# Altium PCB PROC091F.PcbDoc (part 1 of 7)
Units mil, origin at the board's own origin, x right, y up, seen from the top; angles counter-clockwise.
Board outline 3590.95 x 906.17 mil, 8 copper layers (Top Layer, GND1, Sig1, PWR1, PWR2, Sig2, GND2, Bottom Layer), stack 63.146 mil thick; 420 components, 316 nets, 1432 pads, 774 vias.
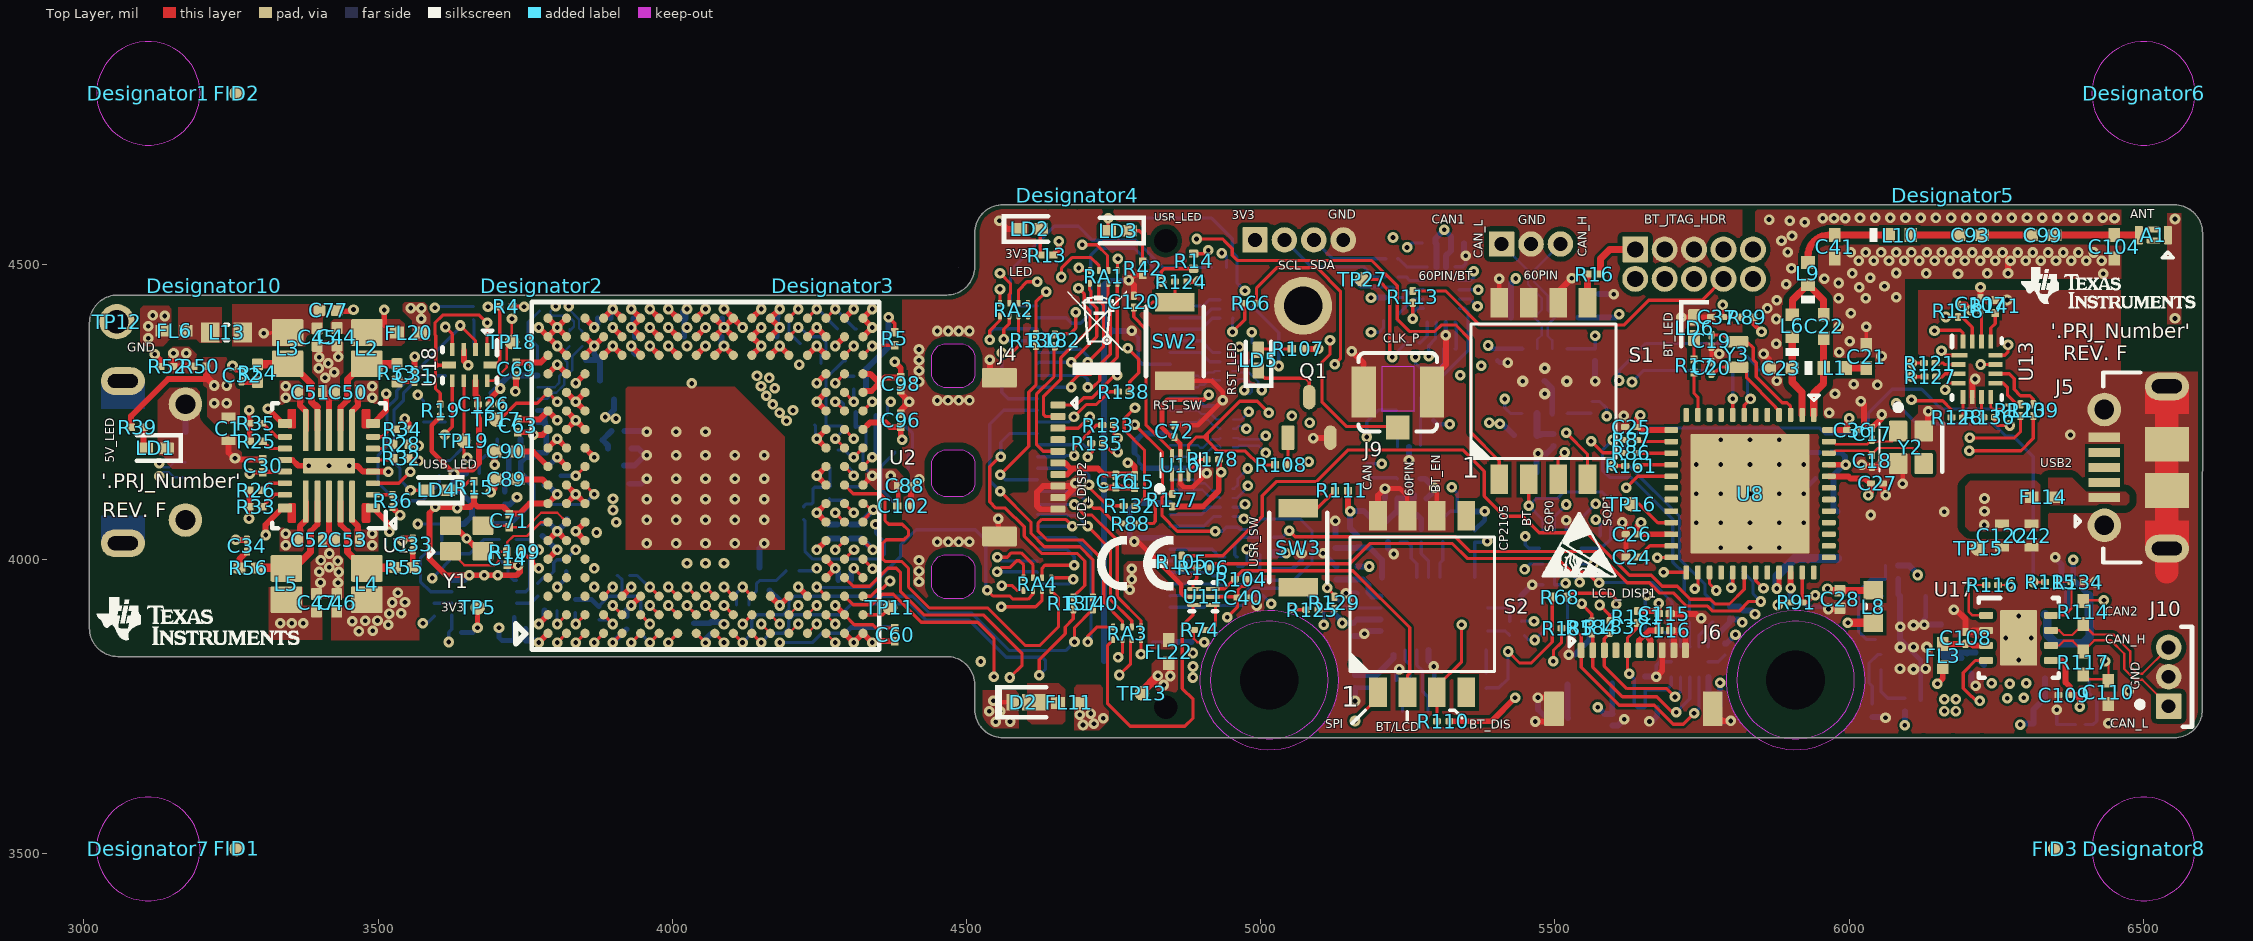
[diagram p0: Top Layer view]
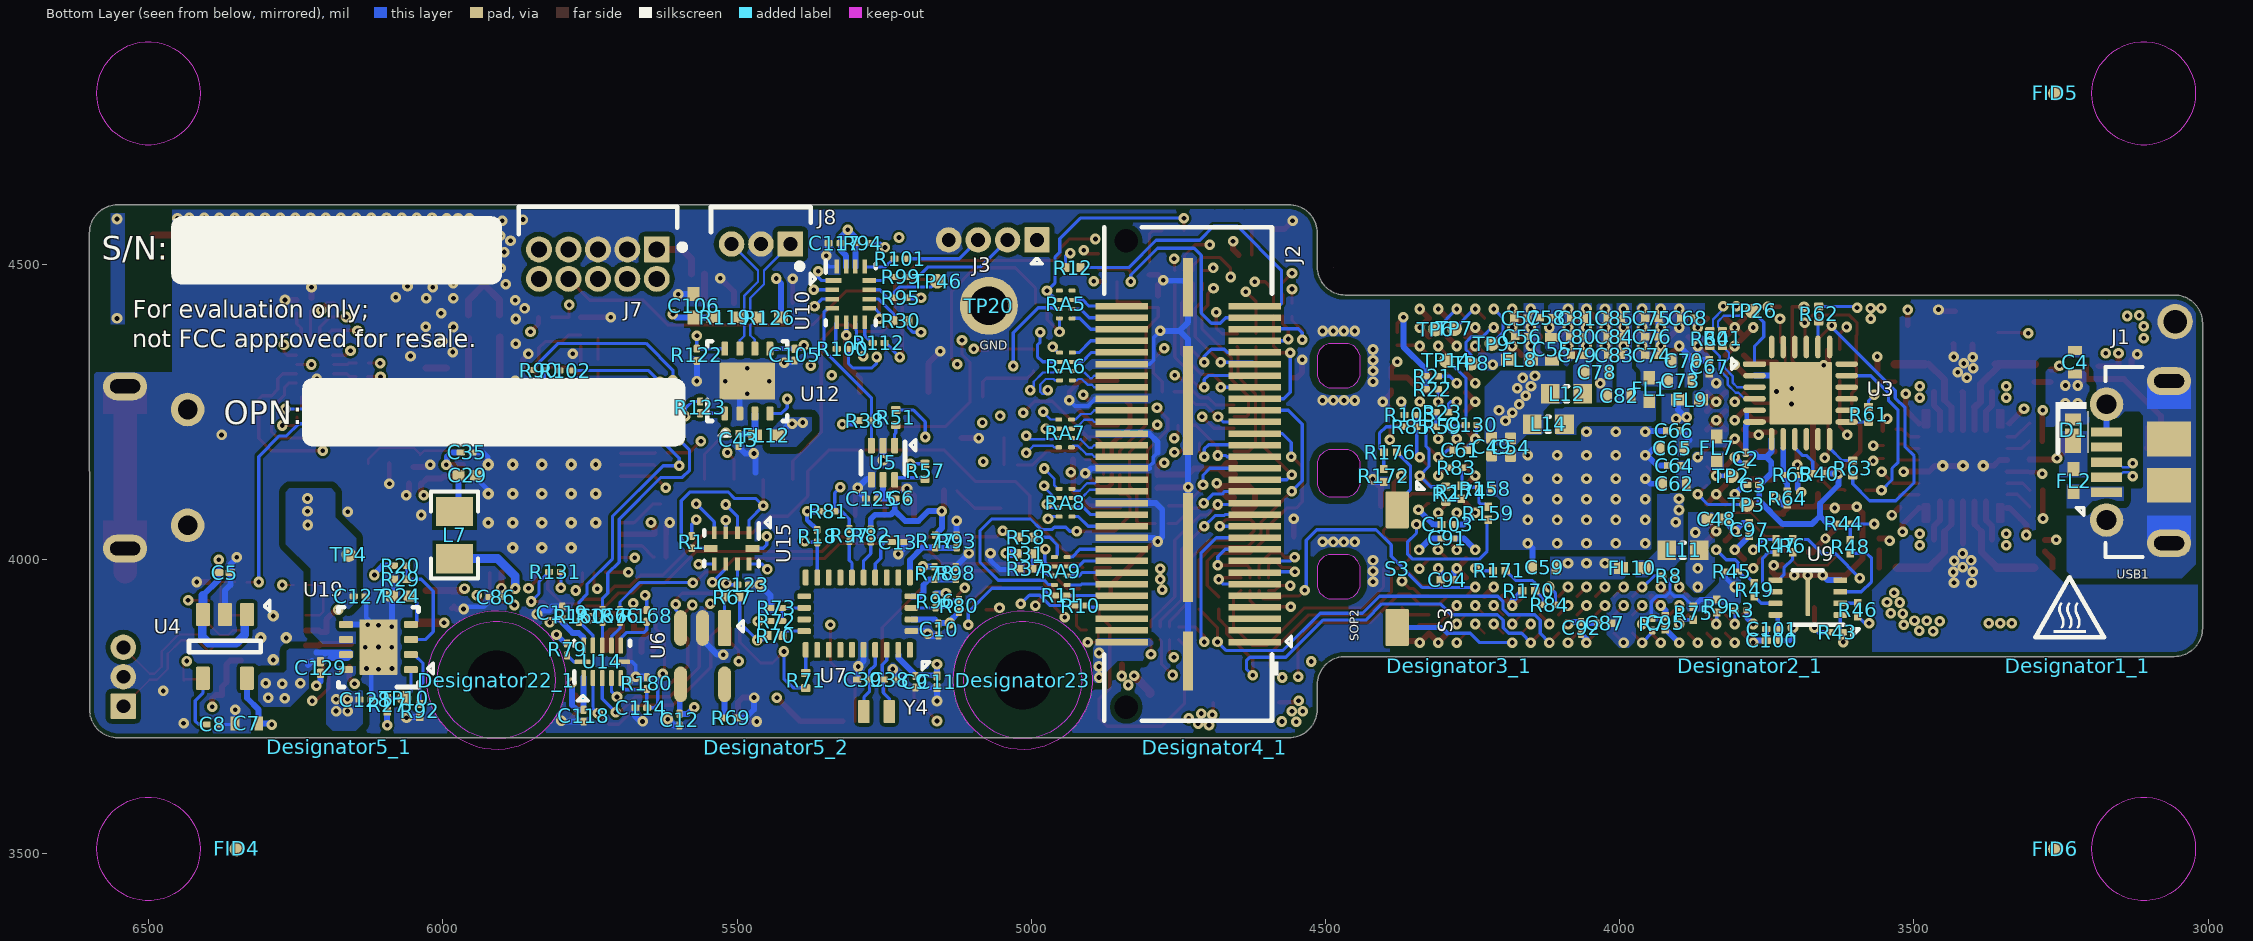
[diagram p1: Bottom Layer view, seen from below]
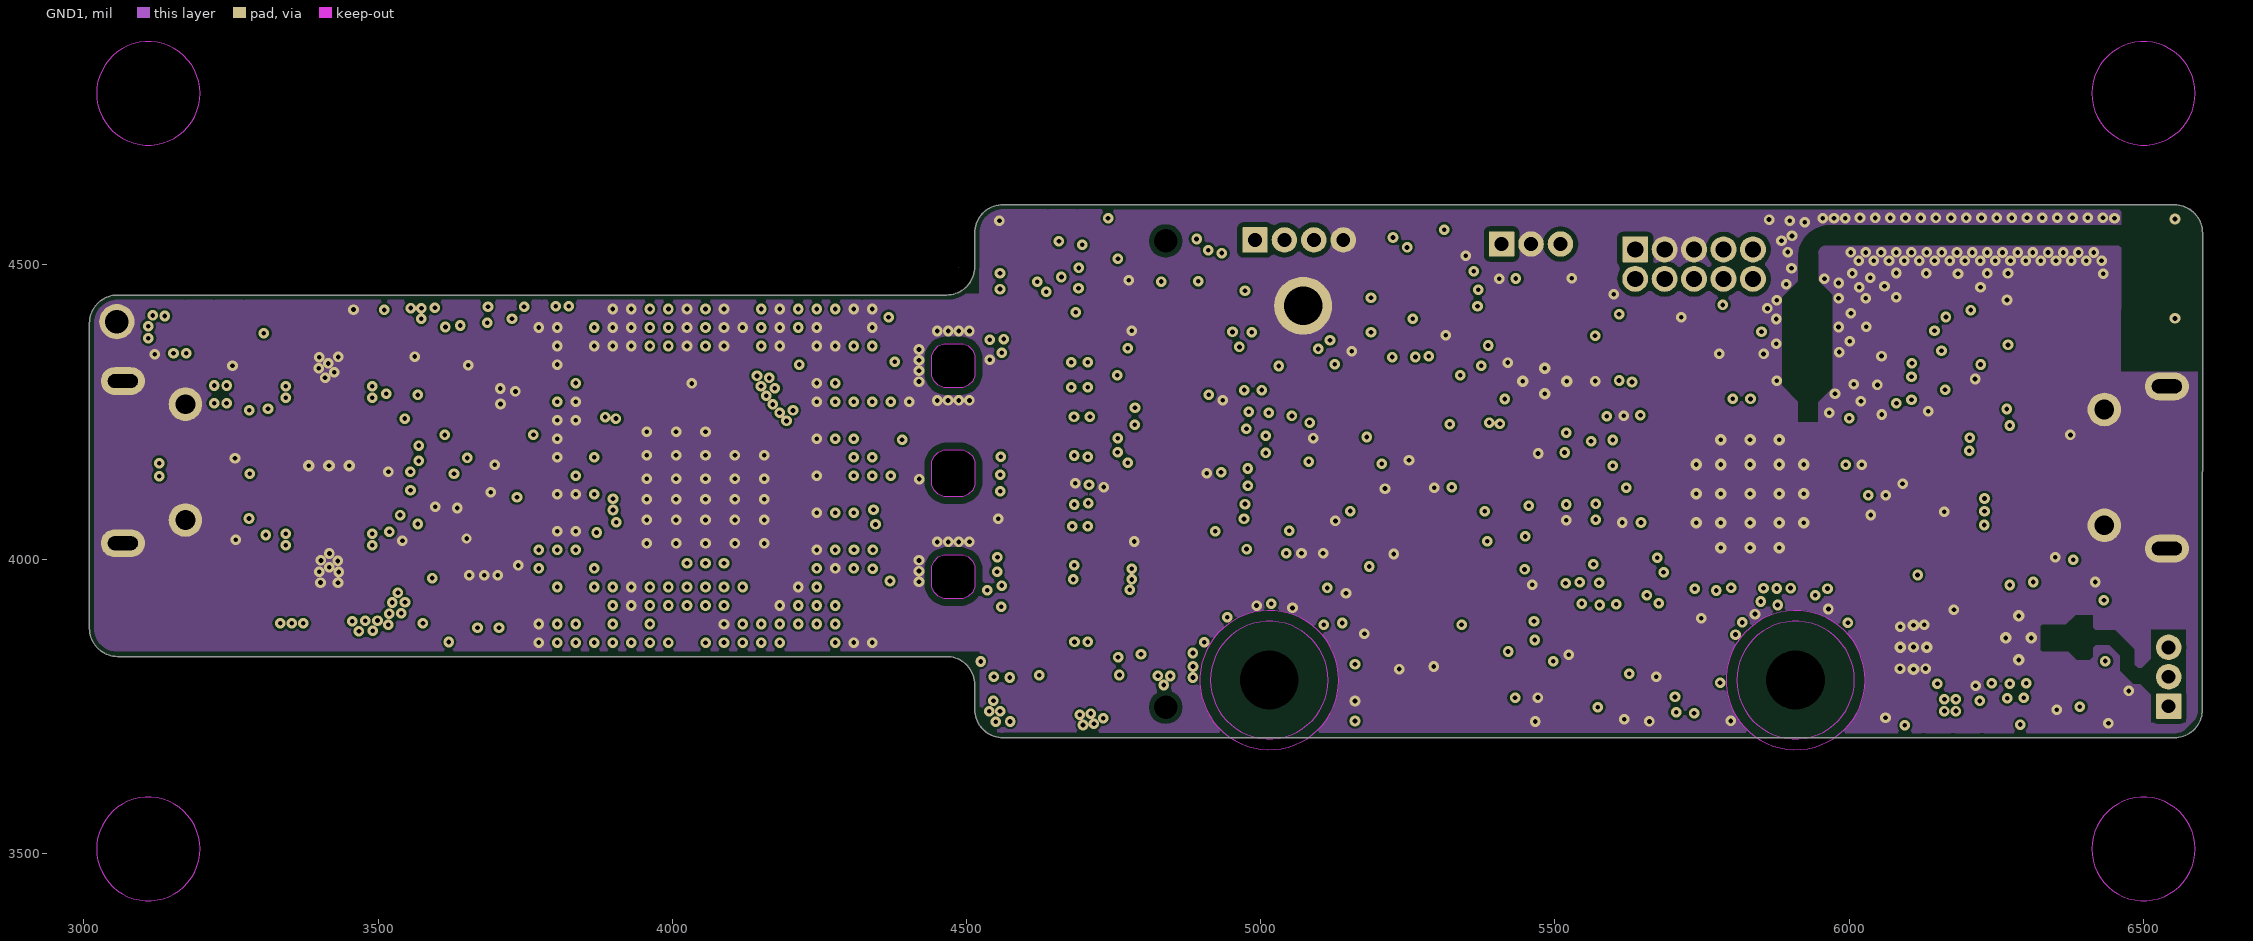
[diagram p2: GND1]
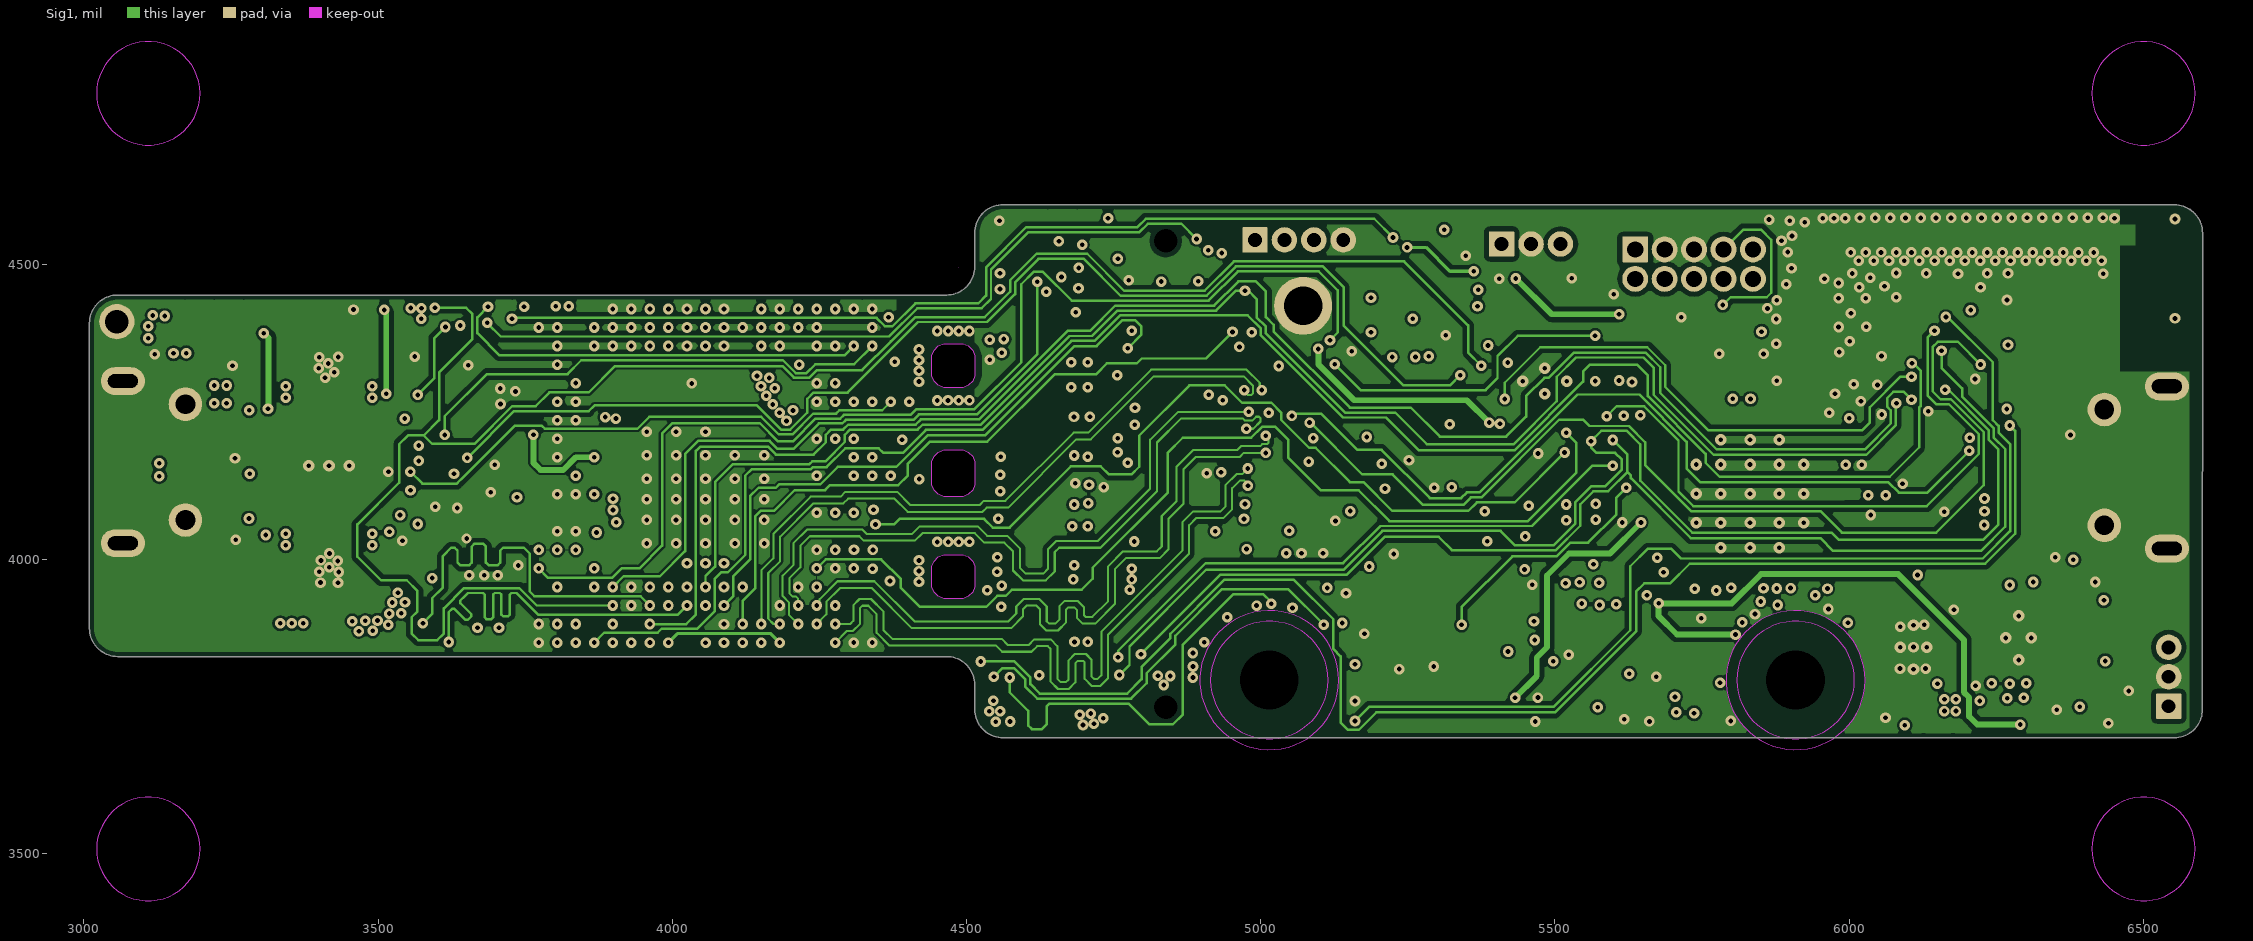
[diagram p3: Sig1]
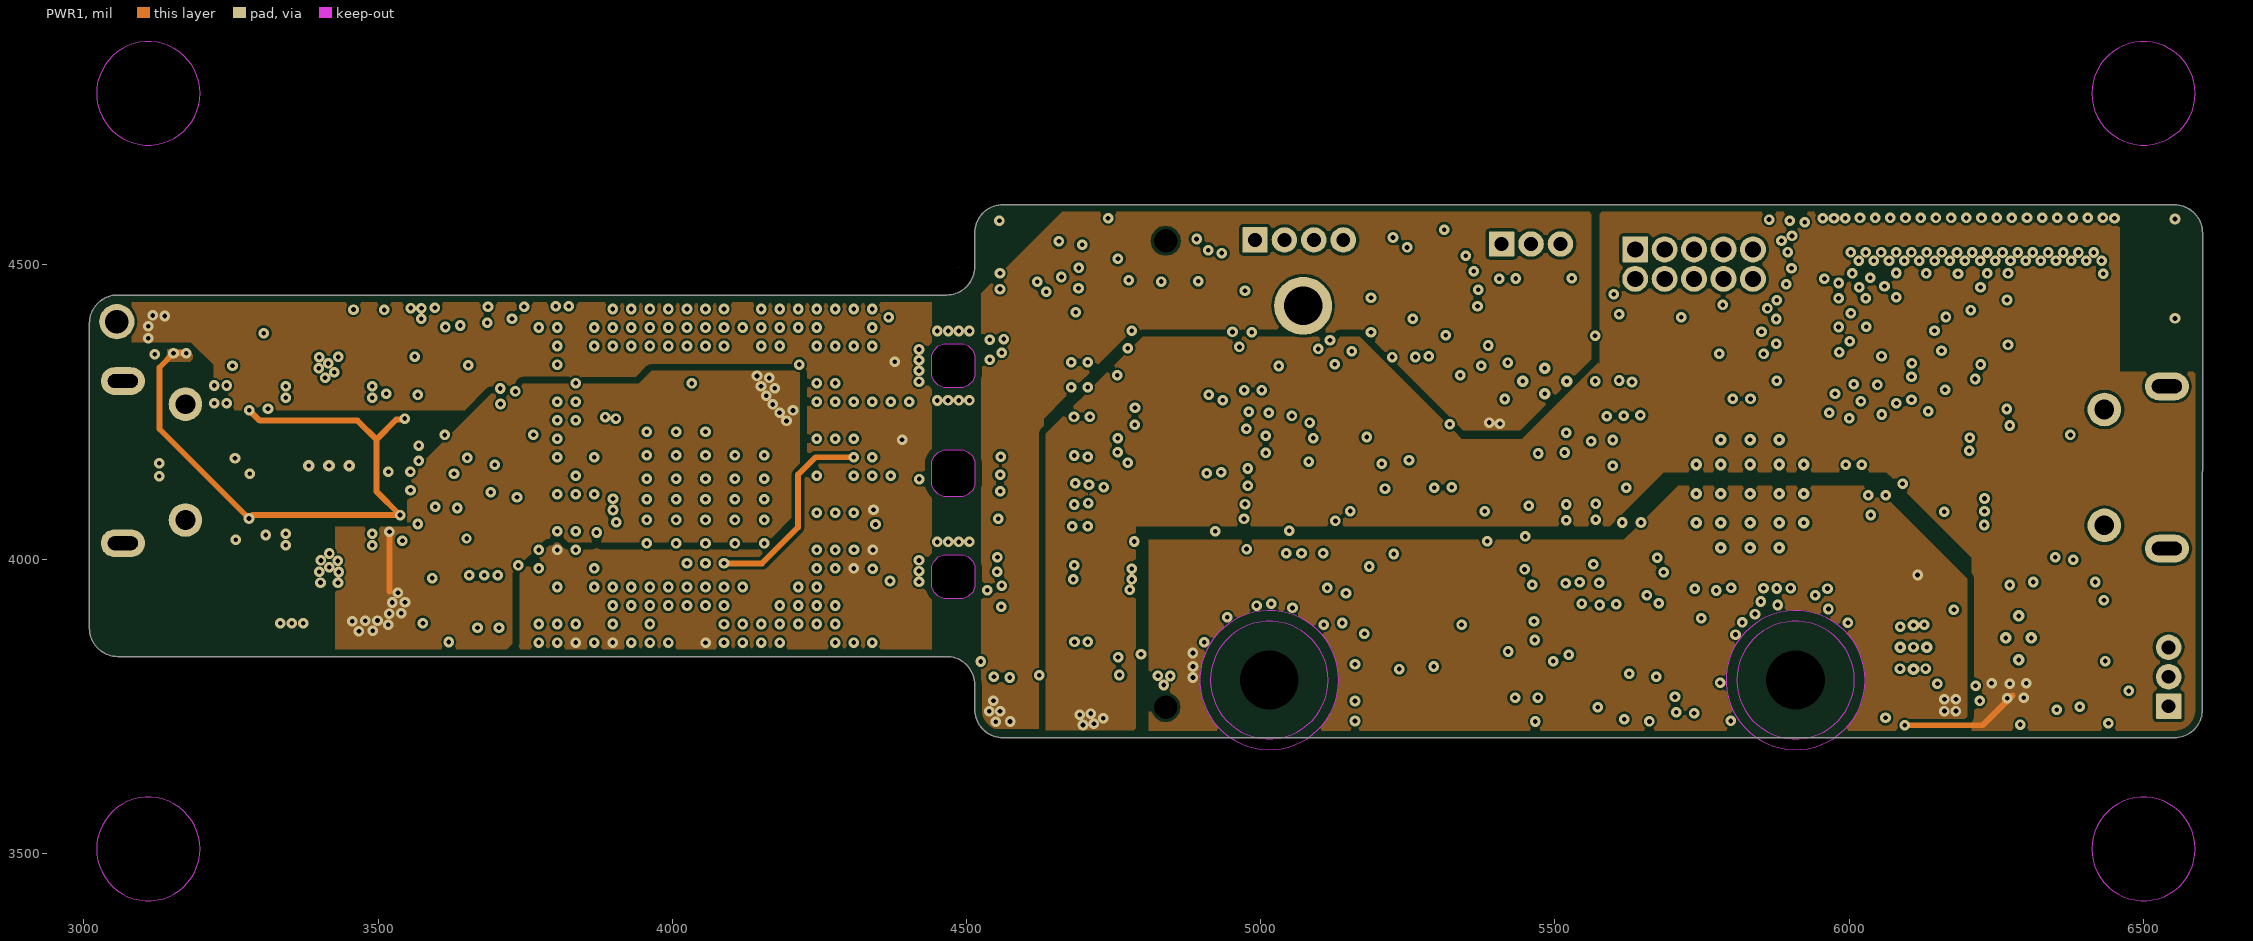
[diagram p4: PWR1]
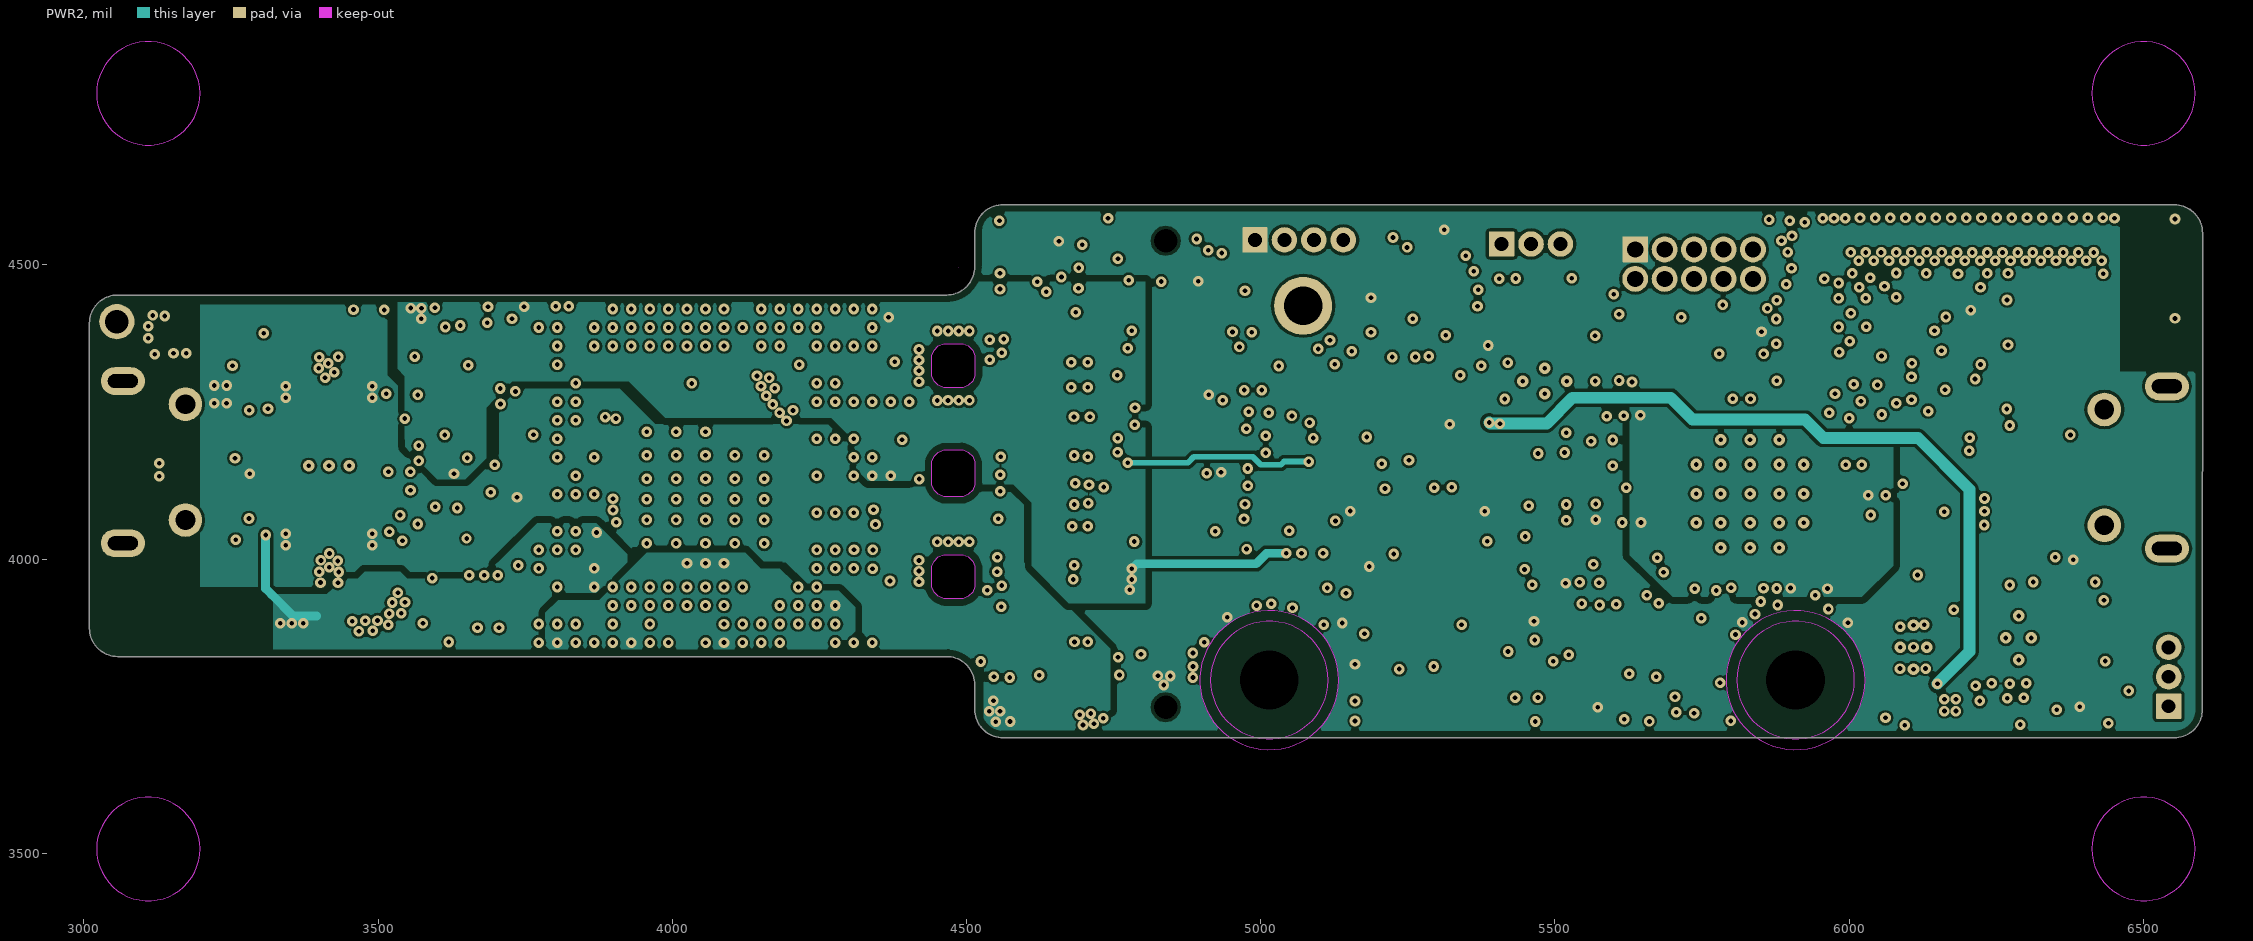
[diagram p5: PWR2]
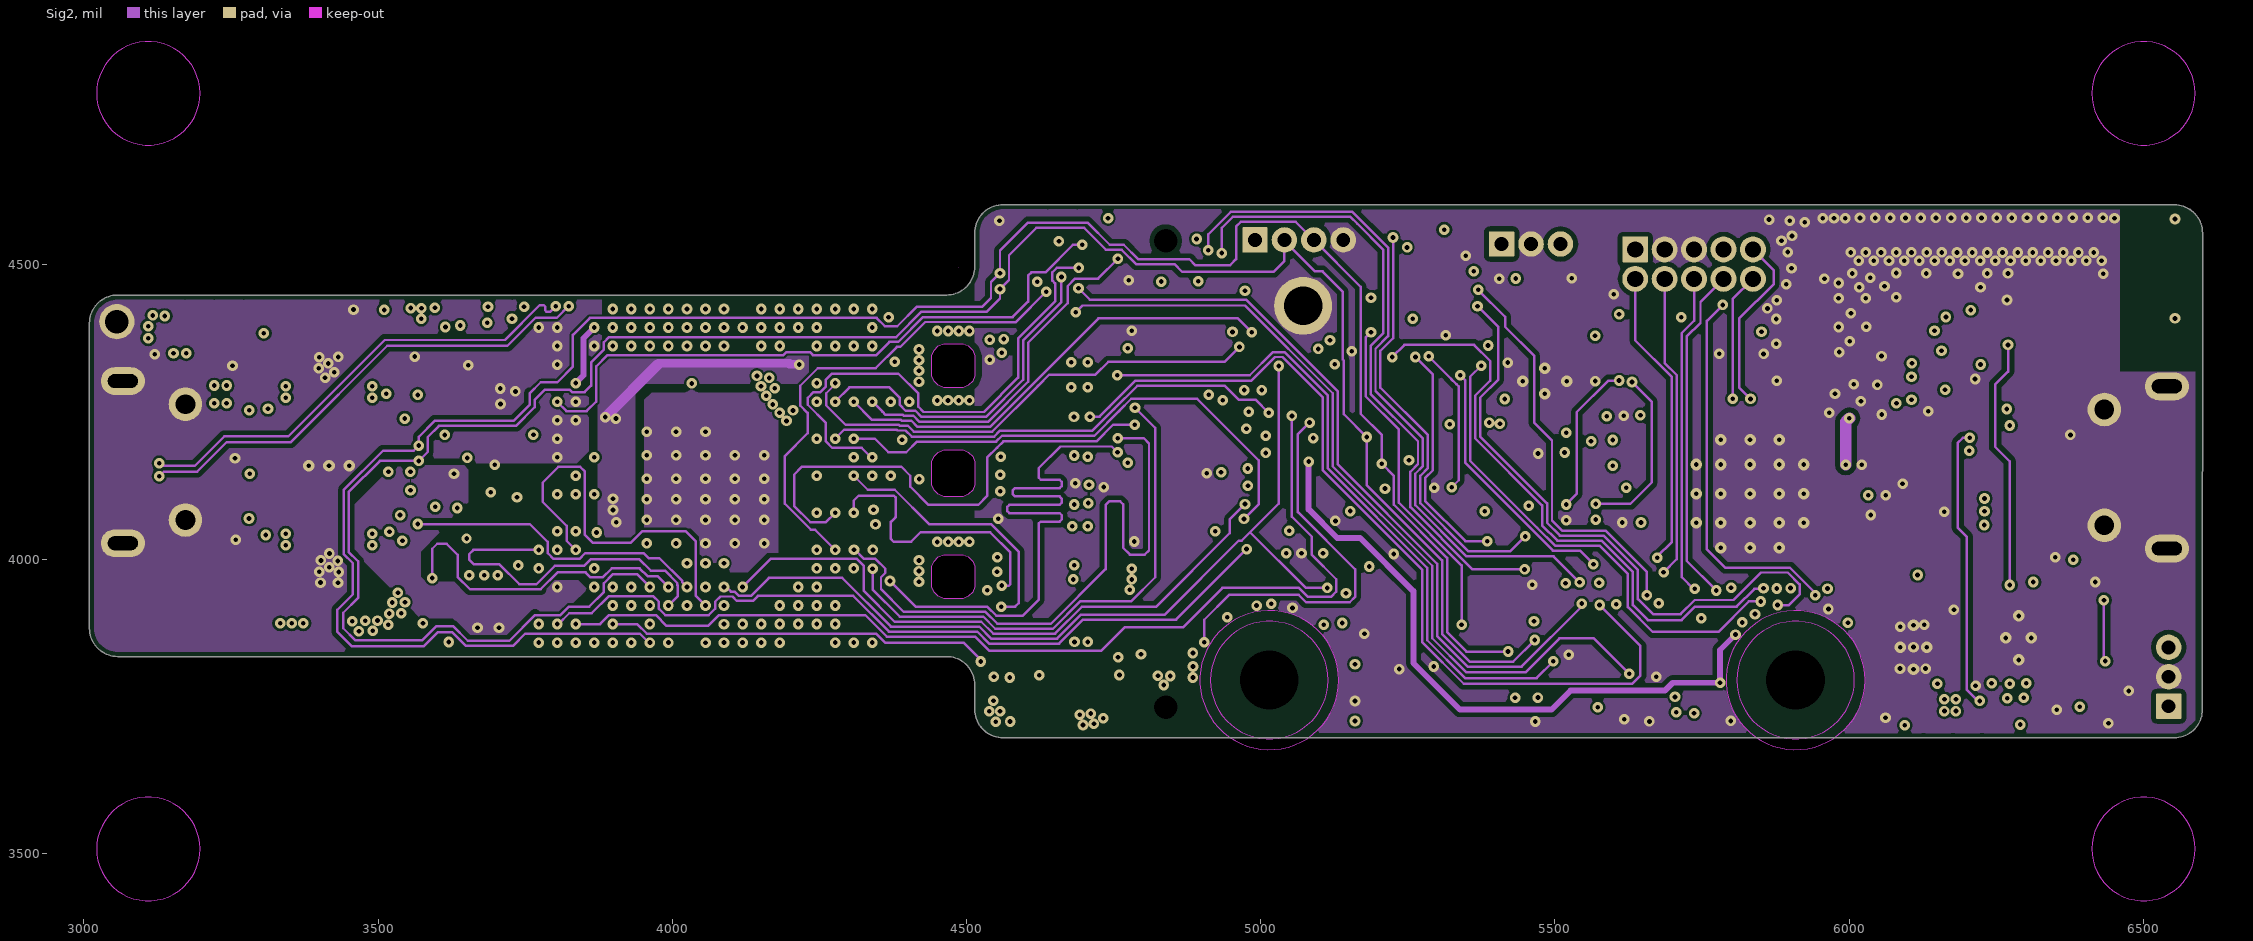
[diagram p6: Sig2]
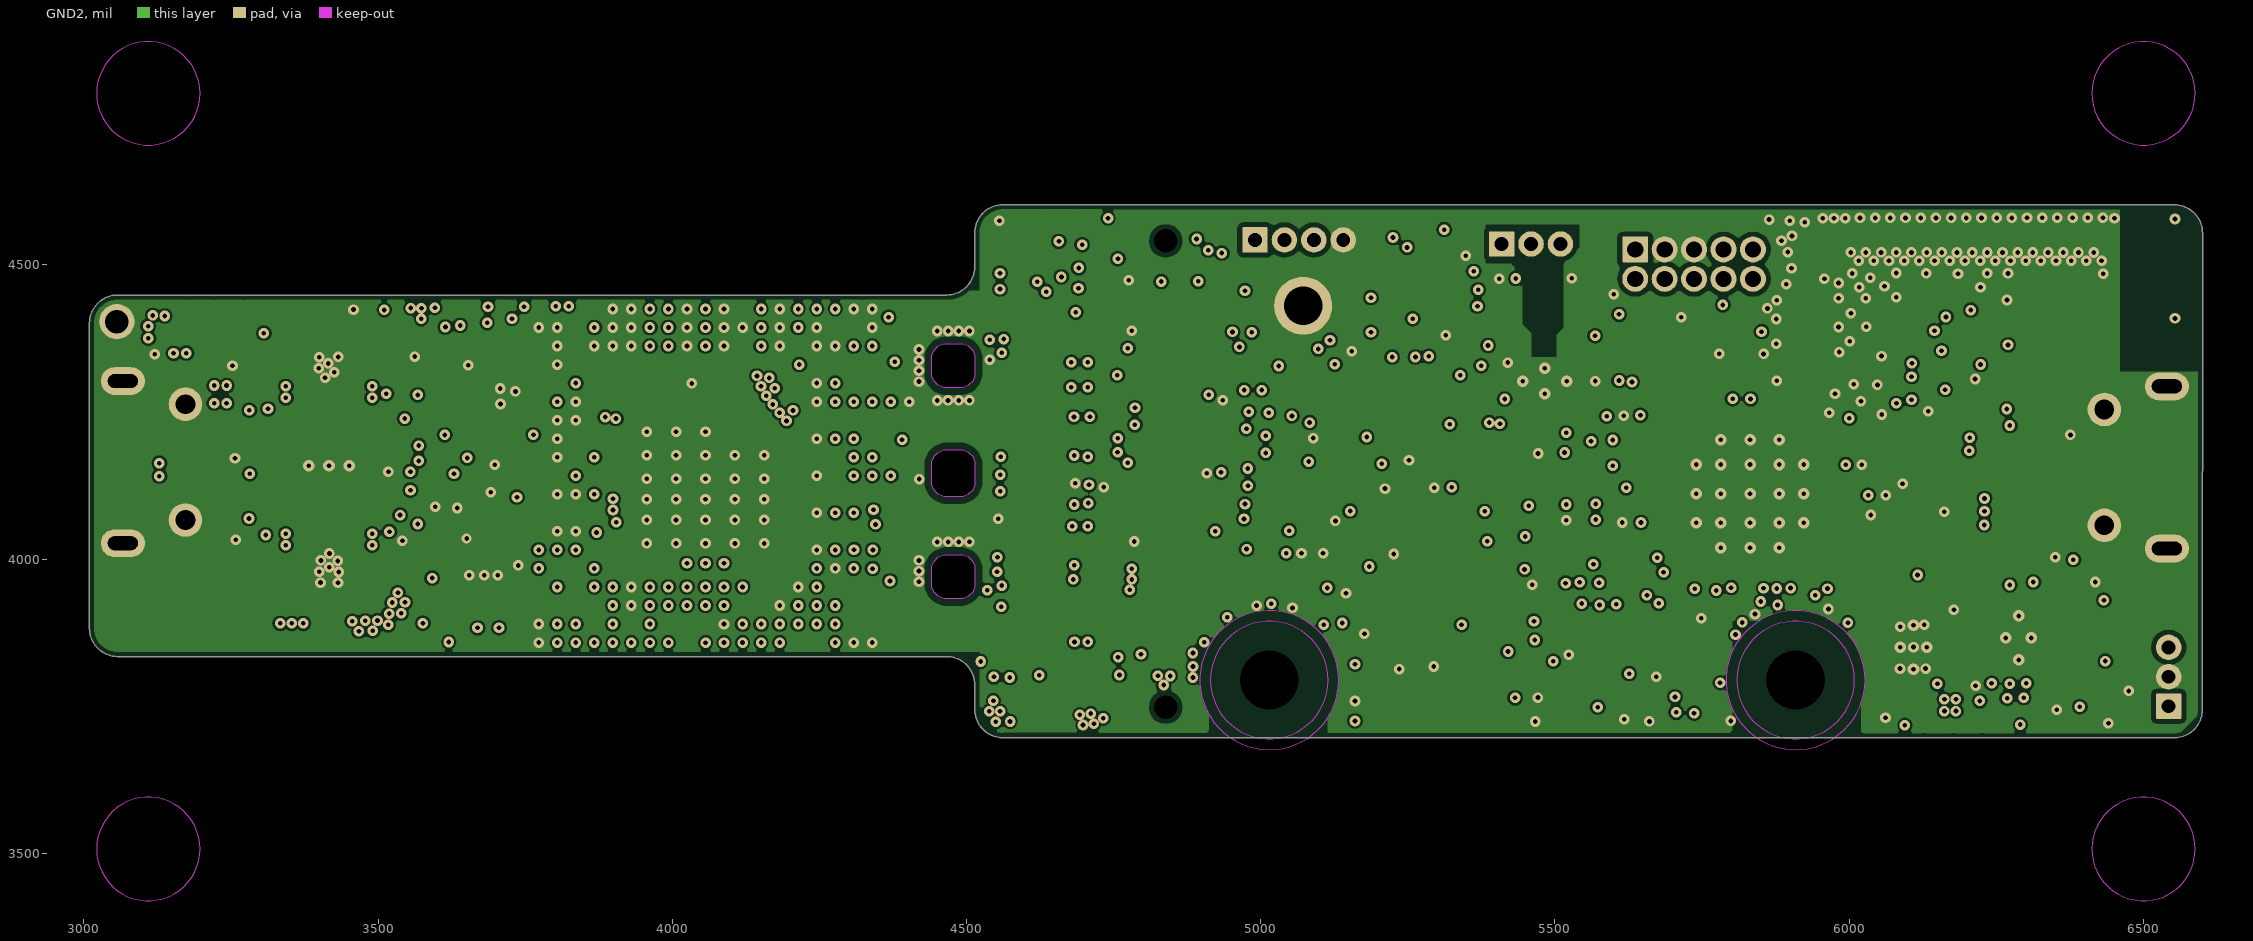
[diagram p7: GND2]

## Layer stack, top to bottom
Top Solder: solder mask 0.5, Solder Resist, Dk 3.5
Top Layer: signal copper 1.373
Dielectric1: core 3.7, FR-4 High Tg, Dk 4.2
GND1: signal copper 2.4
Dielectric3: dielectric 4.5, FR-4 High Tg, Dk 4.2
Sig1: signal copper 1.2
Dielectric2: dielectric 12, FR-4 High Tg, Dk 4.2
PWR1: signal copper 2.4
Dielectric4: dielectric 8, FR-4 High Tg, Dk 4.2
PWR2: signal copper 2.4
Dielectric5: dielectric 12, FR-4 High Tg, Dk 4.2
Sig2: signal copper 1.2
Dielectric8: dielectric 4.5, FR-4 High Tg, Dk 4.2
GND2: signal copper 2.4
Dielectric9: dielectric 3.7, FR-4 High Tg, Dk 4.2
Bottom Layer: signal copper 1.373
Bottom Solder: solder mask 0.5, Solder Resist, Dk 3.5

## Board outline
3057.58,3834.46 4466.14,3834.46 cw(c4466.14,3786.46) 4514.14,3786.46 4514.14,3744.46 ccw(c4562.14,3744.46) 4562.14,3696.46 4562.14,3696.51 6552.27,3696.2 ccw(c6552.27,3744.2) 6600.27,3744.2 6600.29,3744.2 6600.53,4554.1 ccw(c6552.53,4554.1) 6552.53,4602.1 6552.53,4602.08 4562.15,4602.33 4562.15,4602.37 ccw(c4562.15,4554.37) 4514.15,4554.37 4514.15,4496.76 cw(c4466.15,4496.76) 4466.15,4448.76 3057.58,4448.76 ccw(c3057.58,4400.76) 3009.58,4400.76 3009.58,3882.46 ccw(c3057.58,3882.46)
cut-out: 4466.37,4365.95 4494.11,4365.95 4503.29,4362.14 4510.33,4355.11 4514.13,4345.92 4514.13,4340.95 4514.13,4316.3 4514.13,4311.32 4510.33,4302.14 4503.29,4295.1 4494.11,4291.3 4489.13,4291.3 4461.39,4291.3 4452.2,4295.1 4445.17,4302.14 4441.37,4311.32 4441.37,4316.3 4441.37,4340.95 4441.37,4345.92 4445.17,4355.11 4452.2,4362.14 4461.39,4365.95 4466.37,4365.95
cut-out: 4489.13,4185.46 4494.1,4185.46 4503.29,4181.66 4510.32,4174.62 4514.13,4165.44 4514.13,4160.46 4514.13,4131.32 4514.13,4126.35 4510.32,4117.16 4503.29,4110.12 4494.1,4106.32 4489.13,4106.32 4466.36,4106.32 4461.39,4106.32 4452.2,4110.12 4445.17,4117.16 4441.36,4126.35 4441.36,4131.32 4441.36,4160.46 4441.36,4165.44 4445.17,4174.62 4452.2,4181.66 4461.39,4185.46 4489.13,4185.46
cut-out: 4466.36,4007.54 4494.1,4007.54 4503.28,4003.73 4510.32,3996.7 4514.12,3987.51 4514.12,3982.54 4514.12,3957.89 4514.12,3952.91 4510.32,3943.73 4503.28,3936.69 4494.1,3932.89 4489.12,3932.89 4461.38,3932.89 4452.19,3936.69 4445.16,3943.73 4441.36,3952.91 4441.36,3957.89 4441.36,3982.54 4441.36,3987.51 4445.16,3996.7 4452.19,4003.73 4461.38,4007.54 4466.36,4007.54
cut-out: 4477.74,4007.54
cut-out: 4486.41,4495.33

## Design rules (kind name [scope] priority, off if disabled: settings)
AcuteAngle [All] p1: minimum=4.50000000000000E+0001 checktracksonly=TRUE
AssemblyTestPointUsage [All] p1: valid=2
BoardOutlineClearance BoardOutlineClearance_1 [InNet('GND')] p1: gap=8 ignorepadtopadclearanceinfootprint=FALSE
BoardOutlineClearance [NOT(OnTopSilkscreen OR OnBottomSilkscreen)] p2: gap=12 ignorepadtopadclearanceinfootprint=FALSE except(0: Text-OutlineEdge)
Clearance Keepout [(OnLayer('Keep-Out Layer'))] p1: gap=0.01 ignorepadtopadclearanceinfootprint=FALSE except(5.9: THPad-THPad; 7: Arc-THPad Track-THPad THPad-Via; 8: THPad-Fill THPad-Poly THPad-Region)
Clearance RF_TRACE [InNetClass('RF')] p2: gap=4 ignorepadtopadclearanceinfootprint=FALSE except(0: Arc-Hole Track-Hole SMDPad-Hole THPad-Hole Via-Hole Fill-Hole Poly-Hole Region-Hole Text-Hole; 2: Arc-Text Track-Text SMDPad-Text THPad-Text Via-Text Fill-Text Poly-Text Region-Text Text-Text; 5.9: THPad-THPad; 6: SMDPad-Fill SMDPad-Poly SMDPad-Region Via-Fill Via-Poly Via-Region; 7: Arc-THPad Track-THPad THPad-Via; 8: THPad-Fill THPad-Poly THPad-Region; 10: Arc-Fill Arc-Poly Arc-Region Track-Fill Track-Poly Track-Region; 15: Fill-Fill Fill-Poly Fill-Region Poly-Poly Poly-Region Region-Region)
Clearance AOP_T-B [WithinRoom('BGA') vs OnOutside] p3: gap=4 ignorepadtopadclearanceinfootprint=TRUE except(0: Arc-Hole Track-Hole SMDPad-Hole THPad-Hole Via-Hole Fill-Hole Poly-Hole Region-Hole Text-Hole; 3.8: SMDPad-Via; 3.9: Arc-Via Track-Via; 5.9: THPad-THPad; 7: Arc-THPad Track-THPad THPad-Via; 8: THPad-Fill THPad-Poly THPad-Region Fill-Fill Fill-Poly Fill-Region Poly-Poly Poly-Region Region-Region)
Clearance AOP_Sig [WithinRoom('BGA') AND (OnLayer('sig1') or OnLayer('sig2'))] p4: gap=4 ignorepadtopadclearanceinfootprint=FALSE except(0: Arc-Hole Track-Hole SMDPad-Hole THPad-Hole Via-Hole Fill-Hole Poly-Hole Region-Hole Text-Hole; 3.5: Arc-Arc Arc-Track Arc-Via Arc-Text Track-Track Track-Via Track-Text SMDPad-Text THPad-Text Via-Via Via-Text Fill-Text Poly-Text Region-Text Text-Text; 3.8: SMDPad-Via; 5.9: THPad-THPad; 7: Arc-THPad Track-THPad THPad-Via; 8: SMDPad-THPad THPad-Fill THPad-Poly THPad-Region; 15: Fill-Fill Fill-Poly Fill-Region Poly-Poly Poly-Region Region-Region)
Clearance 50E_INNERlayer [(OnLayer('sig1') or OnLayer('Sig2'))] p5: gap=4.2 ignorepadtopadclearanceinfootprint=TRUE except(0: Arc-Hole Track-Hole SMDPad-Hole THPad-Hole Via-Hole Fill-Hole Poly-Hole Region-Hole Text-Hole; 2: SMDPad-Text Fill-Text Poly-Text Region-Text Text-Text; 5.9: THPad-THPad; 6: SMDPad-Fill SMDPad-Poly SMDPad-Region; 7: Arc-THPad Track-THPad THPad-Via; 8: Arc-Fill Arc-Poly Arc-Region Track-Fill Track-Poly Track-Region THPad-Fill THPad-Poly THPad-Region; 12: Fill-Fill Fill-Poly Fill-Region Poly-Poly Poly-Region Region-Region)
Clearance INNERlayer [(OnLayer('pwr1') or OnLayer('pwr2'))] p6: gap=8 ignorepadtopadclearanceinfootprint=TRUE except(0: Arc-Hole Track-Hole SMDPad-Hole THPad-Hole Via-Hole Fill-Hole Poly-Hole Region-Hole Text-Hole; 2: SMDPad-Text Fill-Text Poly-Text Region-Text Text-Text; 4: Via-Fill Via-Poly Via-Region; 4.2: Arc-Text Track-Text THPad-Text Via-Via Via-Text; 5: THPad-Fill THPad-Poly THPad-Region; 5.9: THPad-THPad; 6: Arc-Via Arc-Fill Arc-Poly Arc-Region Track-Via Track-Fill Track-Poly Track-Region; 7: THPad-Via; 12: Fill-Fill Fill-Poly Fill-Region Poly-Poly Poly-Region Region-Region)
Clearance 100E [InDifferentialPairClass('100E')] p7: gap=8 ignorepadtopadclearanceinfootprint=FALSE except(0: Arc-Hole Track-Hole SMDPad-Hole THPad-Hole Via-Hole Fill-Hole Poly-Hole Region-Hole Text-Hole; 2: Arc-Text Track-Text THPad-Text Via-Text Fill-Text Poly-Text Region-Text Text-Text; 4: Arc-SMDPad Track-SMDPad SMDPad-SMDPad SMDPad-THPad SMDPad-Via SMDPad-Text Via-Via Via-Fill Via-Poly Via-Region; 5: Arc-Via Track-Via; 5.9: THPad-THPad; 6: SMDPad-Fill SMDPad-Poly SMDPad-Region Fill-Fill Fill-Poly Fill-Region Poly-Poly Poly-Region Region-Region; 7: Arc-THPad Track-THPad THPad-Via)
Clearance 90E_OUTSIDE [InDifferentialPairClass('90E') vs OnOutside] p8: gap=6 ignorepadtopadclearanceinfootprint=TRUE except(0: Arc-Hole Track-Hole SMDPad-Hole THPad-Hole Via-Hole Fill-Fill Fill-Poly Fill-Region Fill-Hole Poly-Poly Poly-Region Poly-Hole Region-Region Region-Hole Text-Hole; 2: Arc-Text Track-Text SMDPad-Text THPad-Text Via-Text Fill-Text Poly-Text Region-Text Text-Text; 3.8: SMDPad-Via; 4: Arc-SMDPad Track-SMDPad SMDPad-SMDPad Via-Via Via-Fill Via-Poly Via-Region; 4.5: Arc-Arc Arc-Track Arc-Via Track-Track Track-Via; 5.9: THPad-THPad; 7: Arc-THPad Track-THPad SMDPad-THPad THPad-Via; 8: THPad-Fill THPad-Poly THPad-Region)
Clearance [All] p9: gap=1 ignorepadtopadclearanceinfootprint=TRUE except(0: Arc-Hole Track-Hole SMDPad-Hole THPad-Hole Via-Hole Fill-Hole Poly-Hole Region-Hole Text-Hole; 4: SMDPad-SMDPad SMDPad-Via Via-Via Via-Fill Via-Poly Via-Region; 5: Arc-SMDPad Arc-Fill Arc-Poly Arc-Region Track-SMDPad Track-Fill Track-Poly Track-Region; 5.9: THPad-THPad; 6: Arc-Arc Arc-Track Arc-Via Track-Track Track-Via SMDPad-Fill SMDPad-Poly SMDPad-Region; 7: Arc-THPad Track-THPad SMDPad-THPad THPad-Via; 8: THPad-Fill THPad-Poly THPad-Region; 12: Fill-Fill Fill-Poly Fill-Region Poly-Poly Poly-Region Region-Region)
Clearance "SAME NET" [All] p10: gap=0 ignorepadtopadclearanceinfootprint=FALSE except(0.5: SMDPad-Text; 5.9: THPad-THPad)
ComponentClearance ComponentClearance_R199_187 [InComponent('R199') vs InComponent('R187')] p1: gap=-1 collisioncheckmode=3 verticalgap=10 showdistances=FALSE
ComponentClearance ComponentClearance_R188_204 [InComponent('R188') vs InComponent('R204')] p2: gap=-1 collisioncheckmode=3 verticalgap=10 showdistances=FALSE
ComponentClearance [All] p3: gap=1 collisioncheckmode=3 verticalgap=10 showdistances=FALSE
ComponentClearance ComponentClearance_MountingHoles_FiducialMarks [InComponentClass('Mounting Holes') vs InComponentClass('FiducialMark')] p4: gap=50 collisioncheckmode=3 verticalgap=10 showdistances=FALSE
ComponentClearance ComponentClearance_Shunt [InComponentClass('Header') vs InComponentClass('Shunt')] p5: gap=1 collisioncheckmode=3 verticalgap=0 showdistances=FALSE
ComponentClearance ComponentClearance_Logo [InComponentClass('Logo')] p6: gap=50 collisioncheckmode=3 verticalgap=10 showdistances=FALSE
ComponentClearance ComponentClearance_ScrewToNut [(HasFootprint('NY PMS 440 0025 PH')) vs (HasFootprint('Keystone_1902C'))] p7: gap=5 collisioncheckmode=3 verticalgap=10 showdistances=FALSE
ComponentClearance ComponentClearance_MountingHoles [InComponentClass('Mounting Holes')] p8: gap=20 collisioncheckmode=3 verticalgap=100000 showdistances=FALSE
ComponentClearance ComponentClearance_SmallPassives [HasFootprint('0201*') or HasFootprint('0402*') or HasFootprint('0508') or HasFootprint('0603*') or HasFootprint('0612') or HasFootprint('0805*') or HasFootprint('0815*') or HasFootprint('0830*') or HasFootprint('1206*') or HasFootprint('1210*') or HasFootprint('1808*') or HasFootprint('1812*') or HasFootprint('1825*') or HasFootprint('2010*') or HasFootprint('2220*') or HasFootprint('2225*') or HasFootprint('2512*') or HasFootprint('2728*') or HasFootprint('3518*') vs HasFootprint('0201*') or HasFootprint('0402*') or HasFootprint('0508') or HasFootprint('0603*') or HasFootprint('0612') or HasFootprint('0805*') or HasFootprint('0815*') or HasFootprint('0830*') or HasFootprint('1206*') or HasFootprint('1210*') or HasFootprint('1808*') or HasFootprint('1812*') or HasFootprint('1825*') or HasFootprint('2010*') or HasFootprint('2220*') or HasFootprint('2225*') or HasFootprint('2512*') or HasFootprint('2728*') or HasFootprint('3518*')] p9: gap=10 collisioncheckmode=3 verticalgap=10 showdistances=FALSE
ComponentClearance ComponentClearance_THtoSMT [IsThruComponent vs IsSMTComponent] p10: gap=5 collisioncheckmode=3 verticalgap=20 showdistances=FALSE
ComponentClearance ComponentClearance_THtoTH [IsThruComponent vs IsThruComponent] p11: gap=20 collisioncheckmode=3 verticalgap=30 showdistances=FALSE
DiffPairsRouting Diff_100E [InDifferentialPairClass('100E')] p1: maxlimit=10 minlimit=7 mostfreqgap=10 toplayer_maxgap=7 toplayer_prefgap=7 toplayer_minwidth=4 toplayer_maxwidth=4 toplayer_prefwidth=4 midlayer1_mingap=10 midlayer1_minwidth=15 midlayer1_maxwidth=15 midlayer1_prefwidth=15 midlayer2_mingap=8 midlayer2_maxgap=8 midlayer2_prefgap=8 midlayer2_minwidth=3.5 midlayer2_maxwidth=3.5 midlayer2_prefwidth=3.5 midlayer3_mingap=10 midlayer3_minwidth=15 midlayer3_maxwidth=15 midlayer3_prefwidth=15 midlayer6_mingap=10 midlayer6_minwidth=15 midlayer6_maxwidth=15 midlayer6_prefwidth=15 midlayer7_mingap=8 midlayer7_maxgap=8 midlayer7_prefgap=8 midlayer7_minwidth=3.5 midlayer7_maxwidth=3.5 midlayer7_prefwidth=3.5 midlayer8_mingap=10 midlayer8_minwidth=15 midlayer8_maxwidth=15 midlayer8_prefwidth=15 bottomlayer_maxgap=7 bottomlayer_prefgap=7 bottomlayer_minwidth=4 bottomlayer_maxwidth=4 bottomlayer_prefwidth=4 maxuncoupledlength=500
DiffPairsRouting Diff_90E [InDifferentialPairClass('90E')] p2: maxlimit=100 minlimit=4.5 mostfreqgap=10 toplayer_maxgap=4.5 toplayer_prefgap=4.5 toplayer_minwidth=4 toplayer_maxwidth=4 toplayer_prefwidth=4 midlayer1_mingap=10 midlayer1_minwidth=15 midlayer1_maxwidth=15 midlayer1_prefwidth=15 midlayer2_mingap=6 midlayer2_maxgap=6 midlayer2_prefgap=6 midlayer2_minwidth=4 midlayer2_maxwidth=4 midlayer2_prefwidth=4 midlayer3_mingap=10 midlayer3_minwidth=15 midlayer3_maxwidth=15 midlayer3_prefwidth=15 midlayer6_mingap=10 midlayer6_minwidth=15 midlayer6_maxwidth=15 midlayer6_prefwidth=15 midlayer7_mingap=6 midlayer7_maxgap=6 midlayer7_prefgap=6 midlayer7_minwidth=4 midlayer7_maxwidth=4 midlayer7_prefwidth=4 midlayer8_mingap=10 midlayer8_minwidth=15 midlayer8_maxwidth=15 midlayer8_prefwidth=15 bottomlayer_maxgap=4.5 bottomlayer_prefgap=4.5 bottomlayer_minwidth=4 bottomlayer_maxwidth=4 bottomlayer_prefwidth=4 maxuncoupledlength=1000
DiffPairsRouting Diff_120E [All] p3: maxlimit=10 minlimit=6.1 mostfreqgap=10 toplayer_maxgap=6.1 toplayer_prefgap=6.1 toplayer_minwidth=4 toplayer_maxwidth=4 toplayer_prefwidth=4 midlayer1_mingap=10 midlayer1_minwidth=15 midlayer1_maxwidth=15 midlayer1_prefwidth=15 midlayer2_mingap=10 midlayer2_minwidth=15 midlayer2_maxwidth=15 midlayer2_prefwidth=15 midlayer3_mingap=10 midlayer3_minwidth=15 midlayer3_maxwidth=15 midlayer3_prefwidth=15 midlayer6_mingap=10 midlayer6_minwidth=15 midlayer6_maxwidth=15 midlayer6_prefwidth=15 midlayer7_mingap=10 midlayer7_minwidth=15 midlayer7_maxwidth=15 midlayer7_prefwidth=15 midlayer8_mingap=10 midlayer8_minwidth=15 midlayer8_maxwidth=15 midlayer8_prefwidth=15 bottomlayer_maxgap=6.1 bottomlayer_prefgap=6.1 bottomlayer_minwidth=4 bottomlayer_maxwidth=4 bottomlayer_prefwidth=4 maxuncoupledlength=500
FabricationTestPointUsage TestPointUsage [All] p1: valid=2 allowmultiple=FALSE
FabricationTestpoint Testpoint [All] p1: side=3 testpointundercomponent=TRUE minsize=40 maxsize=100 preferedsize=60 minholesize=0 maxholesize=40 preferedholesize=32 testpointgrid=1 allowsidetop=TRUE allowsidebottom=TRUE usegrid=TRUE gridtolerance=0.01
FanoutControl Fanout_LCC [IsLCC] p1: bgadir=Out bgaviamode=Centered fanoutstyle=Auto fanoutdirection=Alternating viagrid=1 // Fanout_LCC (Default Rule)
FanoutControl Fanout_BGA [IsBGA] p2: bgadir=Out bgaviamode=Centered fanoutstyle=Auto fanoutdirection=Alternating viagrid=1 // Fanout_BGA (Default Rule)
FanoutControl Fanout_Default [All] p4: bgadir=Out bgaviamode=Centered fanoutstyle=Auto fanoutdirection=Alternating viagrid=1 // Fanout_Default (Default Rule)
FanoutControl Fanout_Small [(CompPinCount < 5)] p5: bgadir=Out bgaviamode=Centered fanoutstyle=Auto fanoutdirection=OutThenIn viagrid=1 // Fanout_Small (Default Rule)
HoleSize [All] p1: absolutevalues=TRUE maxlimit=251 minlimit=5.9 maxpercent=80.000 minpercent=20.000
MatchedLengths [InNetClass('LVDS_IC')] p1: tolerance=20 checknetsindiffpair=FALSE checkdiffpairvsdiffpair=TRUE checkxsignals=TRUE checkothers=TRUE
MatchedLengths AR_DMM [InxSignalClass('AR_DMM')] p2: tolerance=100 checknetsindiffpair=FALSE checkdiffpairvsdiffpair=TRUE checkxsignals=TRUE checkothers=TRUE
MatchedLengths USB [InxSignalClass('USB')] p3: tolerance=5 checknetsindiffpair=TRUE checkdiffpairvsdiffpair=FALSE checkxsignals=FALSE checkothers=FALSE
MatchedLengths QSPI [InxSignalClass('QSPI')] p4: tolerance=100 checknetsindiffpair=FALSE checkdiffpairvsdiffpair=TRUE checkxsignals=TRUE checkothers=TRUE
MatchedLengths SPI [InxSignalClass('SPI & HOSTINT')] p5: tolerance=200 checknetsindiffpair=FALSE checkdiffpairvsdiffpair=TRUE checkxsignals=TRUE checkothers=TRUE
MatchedLengths JTAG [InxSignalClass('JTAG')] p6: tolerance=100 checknetsindiffpair=FALSE checkdiffpairvsdiffpair=TRUE checkxsignals=TRUE checkothers=TRUE
MinimumAnnularRing MinimumAnnularRing_ThermalPadVias [IsVia and InAnyComponent] p1: minimumring=3
MinimumAnnularRing [All] p2: minimumring=3
MinimumSolderMaskSliver [All] p1: minsoldermaskwidth=3
PlaneConnect [All] p1: planeconnectstyle=Direct reliefexpansion=10 reliefentries=4 reliefconductorwidth=10 reliefairgap=10
PolygonConnect [All] p1: connectstyle=Direct reliefconductorwidth=10 reliefentries=4 polygonreliefangle="90 Angle" airgapwidth=10
RoomDefinition BGA [InComponentClass('60GHz-AOP_IR_FLASH')] p1: confinementstyle=ConfineIn formatcopy=TRUE lockcomponents=FALSE outline 3757.84,4447.61 4382.71,4447.61 4382.71,3834 3757,3834
RoutingVias [All] p1: holewidth=8 width=18 viastyle="Through Hole" minholewidth=7.87 minwidth=17 maxholewidth=40 maxwidth=30
RoutingVias ThermalPadVias [IsVia and InAnyComponent] p2: holewidth=7.87 width=19.68 viastyle="Through Hole" minholewidth=7.87 minwidth=19.68 maxholewidth=12.99 maxwidth=23.62
SilkToBoardRegionClearance [Not ((IsComment or IsDesignator) And (Hide <> 'False')) and not InRegion(1000,500,4000,800)] p1:
SilkToSilkClearance [All] p1: silktosilkclearance=3
SilkToSolderMaskClearance SilkToComponentPadClearance [(IsPad or IsFill or IsRegion) and InAnycomponent] p1: minsilkscreentomaskgap=3 clearancetoexposedcopper=TRUE
SilkToSolderMaskClearance "Silk to Solder Mask Opening" [All] p2: minsilkscreentomaskgap=3 clearancetoexposedcopper=FALSE
SolderMaskExpansion [All] p1: expansion=1.97
Width RF [InNetClass('RF')] p1: maxlimit=100 minlimit=5.5 preferedwidth=10 toplayer_prefwidth=12 midlayer1_minwidth=10 midlayer1_maxwidth=10 midlayer2_minwidth=10 midlayer2_maxwidth=10 midlayer3_minwidth=10 midlayer3_maxwidth=10 midlayer6_minwidth=10 midlayer6_maxwidth=10 midlayer7_minwidth=10 midlayer7_maxwidth=10 midlayer8_minwidth=10 midlayer8_maxwidth=10 bottomlayer_minwidth=10 bottomlayer_maxwidth=10 minimp=50.000000 maximp=50.000000 favimp=50.000000
Width [All] p2: maxlimit=100 minlimit=4 preferedwidth=6 toplayer_maxwidth=40 toplayer_prefwidth=5.5 midlayer1_minwidth=4.2 midlayer1_maxwidth=20 midlayer1_prefwidth=4.2 midlayer2_minwidth=4.2 midlayer2_maxwidth=20 midlayer2_prefwidth=4.2 midlayer7_minwidth=4.2 midlayer7_maxwidth=20 midlayer7_prefwidth=4.2 midlayer8_minwidth=6 midlayer8_prefwidth=10 bottomlayer_maxwidth=40 bottomlayer_prefwidth=5.5 minimp=50.000000 maximp=50.000000 favimp=50.000000
15 further rules are at their usual default settings.

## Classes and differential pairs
net class LVDS_CONN: NetJ2_28 NetJ2_30 NetJ2_34 NetJ2_36 NetJ2_40 NetJ2_42 NetJ2_46 NetJ2_48
net class LVDS_IC: AR_LVDS_0_N AR_LVDS_0_P AR_LVDS_1_N AR_LVDS_1_P AR_LVDS_CLK_N AR_LVDS_CLK_P AR_LVDS_FRCLK_N AR_LVDS_FRCLK_P
differential pair class 120E: CAN CAN2
differential pair class 100E: AR_LVDS_0 AR_LVDS_1 AR_LVDS_CLK AR_LVDS_FRCLK AR_XTAL X48M
differential pair class 90E: NewDifferentialPair1 USB
net class RF: NetA1_4 NetC21_2 NetC22_1 NetC41_1 NetC93_1 NetC93_2 RF_N RF_P
component class PROC091F_RST_GPIOs_I2C: C6 C9 C10 C11 C12 C13 C38 C39 C72 C120 C125 J3 LD2 LD3 LD5 Q1 R13 R18 R38 R42 R51 R57 R67 R68 R69 R70 R71 R72 R73 R77 R78 R80 R81 R82 R93 R96 R97 R98 R107 R108 R111 R124 R125 R129 R177 R178 SW2 SW3 TP15 TP20 U5 U6 U7 U16 Y4
component class PROC091F_PMIC: C30 C31 C32 C33 C34 C44 C45 C46 C47 C48 C49 C50 C51 C52 C53 C54 C77 FL1 FL8 FL9 FL10 FL20 L2 L3 L4 L5 L11 L12 L13 L14 LD1 R25 R26 R28 R31 R32 R33 R34 R35 R36 R37 R39 R50 R52 R53 R54 R55 R56 TP5 TP12 U1
component class PROC091F_HD_CONN_PWR_SW: C127 C128 C129 D2 FL11 FL22 J2 R10 R11 R12 R14 R20 R24 R27 R29 R58 R88 R92 R130 R132 R133 R135 R137 R138 R140 RA1 RA2 RA3 RA4 RA5 RA6 RA7 RA8 RA9 TP10 TP13 U19
component class PROC091F_FLASH_USB_TO_UART: C1 C2 C3 C4 C100 C101 C126 D1 FL2 J1 LD4 R6 R15 R19 R40 R41 R43 R44 R45 R46 R47 R48 R49 R60 R61 R62 R63 R64 R65 TP18 TP19 TP26 U3 U9 U18
component class PROC091F_CAN_INTERFACE: C40 C43 C105 C106 C107 C108 C109 C110 FL3 FL12 J8 J10 R66 R74 R104 R105 R106 R114 R115 R116 R117 R118 R119 R120 R121 R122 R123 R126 R127 R128 R134 R136 R139 R141 U11 U12 U13 U17
component class PROC091F_BT_DISPLAY: A1 C5 C7 C8 C15 C16 C17 C18 C19 C20 C21 C22 C23 C24 C25 C26 C27 C28 C29 C35 C36 C37 C41 C86 C93 C99 C104 C114 C115 C116 C117 C118 C119 J4 J6 J7 L1 L6 L7 L8 L9 L10 LD6 R17 R30 R76 R79 R86 R87 R89 R90 R91 R94 R95 R99 R100 R101 R102 R110 R112 R113 R131 R160 R161 R166 R168 R180 R181 R182 R183 R184 R185 TP16 TP27 TP46 U4 U8 U10 U14 Y2 Y3
component class PROC091F_AOP_PWR: C55 C56 C57 C58 C59 C60 C61 C62 C63 C64 C65 C66 C67 C68 C69 C70 C73 C74 C75 C76 C78 C79 C80 C81 C82 C83 C84 C85 C87 C88 C89 C90 C91 C92 C94 C95 C96 C97 C98 C102 C103 FL6 FL7 TP11
component class PROC091F_AOP_IO: C14 C71 C130 J9 R2 R3 R4 R5 R7 R8 R9 R21 R22 R23 R59 R75 R83 R84 R85 R103 R109 R158 R159 R170 R171 R172 R174 R176 S3 TP2 TP3 TP6 TP7 TP8 TP9 TP14 TP17 U2 Y1
component class PROC091F_ANALOG_MUX: C42 C122 C123 FL14 J5 R1 R16 S1 S2 TP4 U15
component class PROC091F_Hardware: FID1 FID2 FID3 FID4 FID5 FID6 ZZ1 ZZ2 ZZ3 ZZ4 ZZ5.1 ZZ5.2
component class FiducialMark: FID1 FID2 FID3 FID4 FID5 FID6
component class AssemblyNote: ZZ1 ZZ2 ZZ3 ZZ4 ZZ5.1 ZZ5.2
differential pair CAN2: +NetJ10_1 -NetJ10_3
differential pair NewDifferentialPair1: +NetR41_1 -NetR60_1
differential pair USB: +USB_DM -USB_DP
differential pair CAN: +NetJ8_1 -NetJ8_3
differential pair X48M: +X48M_N -X48M_P
differential pair AR_XTAL: +AR_XTAL_N -AR_XTAL_P
differential pair AR_LVDS_FRCLK: +AR_LVDS_FRCLK_N -AR_LVDS_FRCLK_P
differential pair AR_LVDS_CLK: +AR_LVDS_CLK_N -AR_LVDS_CLK_P
differential pair AR_LVDS_1: +AR_LVDS_1_N -AR_LVDS_1_P
differential pair AR_LVDS_0: +AR_LVDS_0_N -AR_LVDS_0_P

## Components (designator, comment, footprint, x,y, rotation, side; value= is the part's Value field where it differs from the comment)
A1 "ANT016008LCS2442MA2" FP-ANT016008LCS2442MA2_SMT_ANT-0 6517.1,4550.46 r180 top
C1 "CL05A106MP5NUNC" 0402_070 3245.8,4221.22 r90 top value=10uF
C2 "GRM033R6YA104KE14D" "FP-GRM033R6YA104KE14D_0201 (0603 Metric)-IPC_C" 3785.88,4170.74 r90 bottom
C3 "GRM033R6YA104KE14D" "FP-GRM033R6YA104KE14D_0201 (0603 Metric)-IPC_C" 3772.95,4125.72 r180 bottom
C4 "CL05A106MP5NUNC" 0402_070 3226.3,4334.4 r90 bottom value=10uF
C5 "CL03A105MO3NRNH" FP-CL03A105MO3NRNH_0201-IPC_C 6371,3977 r180 bottom
C6 "GRM033R6YA104KE14D" "FP-GRM033R6YA104KE14D_0201 (0603 Metric)-IPC_C" 5221.01,4103.02 r0 bottom locked
C7 "CL05A106MP5NUNC" 0402_070 6332.97,3720.79 r0 bottom value=10uF
C8 "CL03A103KA3NNNC" FP-CL03A103KA3NNNC_0201-IPC_C 6391.38,3719.01 r180 bottom
C9 "GRM033R6YA104KE14D" "FP-GRM033R6YA104KE14D_0201 (0603 Metric)-IPC_C" 5197.1,3791.56 r90 bottom locked
C10 "GRM033R6YA104KE14D" "FP-GRM033R6YA104KE14D_0201 (0603 Metric)-IPC_C" 5157.67,3880.39 r90 bottom locked
C11 "CL03A105MO3NRNH" FP-CL03A105MO3NRNH_0201-IPC_C 5160.25,3791.5 r270 bottom locked
C12 "GRM033R6YA104KE14D" "FP-GRM033R6YA104KE14D_0201 (0603 Metric)-IPC_C" 5598.06,3727.05 r90 bottom
C13 "GRM033R6YA104KE14D" "FP-GRM033R6YA104KE14D_0201 (0603 Metric)-IPC_C" 5227.18,4028.9 r0 bottom
C14 "GRM0335C1H4R7BA01D" 0201_033L 3719.34,4001.36 r90 top value=4.7pF
C15 "CL03A105MO3NRNH" FP-CL03A105MO3NRNH_0201-IPC_C 4785.89,4131.62 r270 top locked
C16 "CL03A105MO3NRNH" FP-CL03A105MO3NRNH_0201-IPC_C 4753.82,4132.42 r270 top locked
C17 "GRM0335C1H8R0BA01D" "FP-GRM0335C1H8R0BA01D_0201 (0603 metric)-IPC_C" 6038.8,4212.94 r90 top
C18 "GRM0335C1H8R0BA01D" "FP-GRM0335C1H8R0BA01D_0201 (0603 metric)-IPC_C" 6038.8,4166.75 r270 top
C19 "250R05L120JV4T" FP-250R05L120JV4T_0201-IPC_C 5765.79,4370.87 r270 top
C20 "250R05L120JV4T" FP-250R05L120JV4T_0201-IPC_C 5765.79,4324.98 r90 top
C21 "CL05C120JB5NNNC" 0402L 6028.92,4344.09 r270 top value=12pF
C22 "GCM1555C1H1R0CA16D" 0402L 5956.7,4395.47 r270 top value=1pF
C23 "GCM1555C1H1R0CA16D" 0402L 5883.59,4324.42 r180 top value=1pF
C24 "CL03A105MO3NRNH" FP-CL03A105MO3NRNH_0201-IPC_C 5630.51,4003.46 r180 top
C25 "GRM033R6YA104KE14D" "FP-GRM033R6YA104KE14D_0201 (0603 Metric)-IPC_C" 5629.37,4224.38 r180 top
C26 "GRM033R6YA104KE14D" "FP-GRM033R6YA104KE14D_0201 (0603 Metric)-IPC_C" 5630.37,4042.21 r180 top
C27 "GRM033R6YA104KE14D" "FP-GRM033R6YA104KE14D_0201 (0603 Metric)-IPC_C" 6047.37,4128.46 r0 top
C28 "CL05A226MQ5N6J8" FP-CL05A226MQ5N6J8_0402-IPC_C 5984.12,3931.35 r270 top
C29 "CL05A226MQ5N6J8" FP-CL05A226MQ5N6J8_0402-IPC_C 5958.37,4142.46 r180 bottom
C30 "LMK063BJ224MP-F" 0201_033L 3304,4158.52 r90 top value=0.22uF
C31 "TMK063CG391JT-F" "FP-TMK063CG391JT-F_0201 (0603 Metric)-IPC_C" 3562.13,4311.22 r90 top
C32 "TMK063CG391JT-F" "FP-TMK063CG391JT-F_0201 (0603 Metric)-IPC_C" 3268.13,4312.11 r90 top
C33 "TMK063CG391JT-F" "FP-TMK063CG391JT-F_0201 (0603 Metric)-IPC_C" 3559.04,4025.1 r90 top
C34 "TMK063CG391JT-F" "FP-TMK063CG391JT-F_0201 (0603 Metric)-IPC_C" 3277.23,4022.75 r90 top
C35 "GRM033R6YA104KE14D" "FP-GRM033R6YA104KE14D_0201 (0603 Metric)-IPC_C" 5959.54,4181.25 r180 bottom
C36 "GRM033R6YA104KE14D" "FP-GRM033R6YA104KE14D_0201 (0603 Metric)-IPC_C" 6006.44,4219.38 r0 top
C37 "GRM033R6YA104KE14D" "FP-GRM033R6YA104KE14D_0201 (0603 Metric)-IPC_C" 5775.38,4411.08 r180 top
C38 "250R05L120JV4T" FP-250R05L120JV4T_0201-IPC_C 5240.41,3795.13 r180 bottom locked
C39 "250R05L120JV4T" FP-250R05L120JV4T_0201-IPC_C 5286.16,3795.3 r0 bottom locked
C40 "GRM033R6YA104KE14D" "FP-GRM033R6YA104KE14D_0201 (0603 Metric)-IPC_C" 4970.37,3934.38 r0 top locked
C41 "GCM1555C1H1R0CA16D" 0402L 5975.28,4530.78 r270 top value=1pF
C42 "CL05A106MP5NUNC" 0402_070 6310,4040 r90 top value=10uF
C43 "GRM033R6YA104KE14D" "FP-GRM033R6YA104KE14D_0201 (0603 Metric)-IPC_C" 5497.81,4202.58 r90 bottom
C44 "CL05A226MQ5N6J8" FP-CL05A226MQ5N6J8_0402-IPC_C 3430.22,4377.73 r270 top
C45 "CL05A226MQ5N6J8" FP-CL05A226MQ5N6J8_0402-IPC_C 3396.5,4377.26 r270 top
C46 "CL05A226MQ5N6J8" FP-CL05A226MQ5N6J8_0402-IPC_C 3429.83,3925.6 r90 top
C47 "CL05A226MQ5N6J8" FP-CL05A226MQ5N6J8_0402-IPC_C 3395.41,3925.76 r90 top
C48 "CL05A226MQ5N6J8" FP-CL05A226MQ5N6J8_0402-IPC_C 3836.23,4067.82 r180 bottom
C49 "CL05A226MQ5N6J8" FP-CL05A226MQ5N6J8_0402-IPC_C 4217.54,4191.28 r270 bottom
C50 "CL05A106MP5NUNC" 0402_070 3448.11,4283.77 r180 top value=10uF
C51 "CL05A106MP5NUNC" 0402_070 3385.11,4283.77 r0 top value=10uF
C52 "CL05A106MP5NUNC" 0402_070 3385.11,4033.27 r0 top value=10uF
C53 "CL05A106MP5NUNC" 0402_070 3448.11,4033.27 r180 top value=10uF
C54 "CL05A226MQ5N6J8" FP-CL05A226MQ5N6J8_0402-IPC_C 4185.58,4190.34 r270 bottom
C55 "CL05A106MP5NUNC" 0402_070 4115.16,4356.5 r90 bottom value=10uF
C56 "LMK063BJ224MP-F" 0201_033L 4166.37,4378.24 r0 bottom value=0.22uF
C57 "LMK063BJ224MP-F" 0201_033L 4168.42,4409.4 r0 bottom value=0.22uF
C58 "LMK063BJ224MP-F" 0201_033L 4125.06,4410.16 r180 bottom value=0.22uF
C59 "CL05A106MP5NUNC" 0402_070 4128.3,3985.94 r0 bottom value=10uF
C60 "LMK063BJ224MP-F" 0201_033L 4378.33,3871.66 r270 top value=0.22uF
C61 "LMK063BJ224MP-F" 0201_033L 4270.98,4185.3 r180 bottom value=0.22uF
C62 "CL05A106MP5NUNC" 0402_070 3907,4128 r0 bottom value=10uF
C63 "LMK063BJ224MP-F" 0201_033L 3737.19,4226.49 r90 top value=0.22uF
C64 "LMK063BJ224MP-F" 0201_033L 3907,4159 r0 bottom value=0.22uF
C65 "CL05A106MP5NUNC" 0402_070 3911,4188 r0 bottom value=10uF
C66 "LMK063BJ224MP-F" 0201_033L 3908.02,4218 r0 bottom value=0.22uF
C67 "LMK063BJ224MP-F" 0201_033L 3848,4327 r90 bottom value=0.22uF
C68 "LMK063BJ224MP-F" 0201_033L 3884.37,4409.24 r0 bottom value=0.22uF
C69 "GRM033R61C473KE84D" 0201_033L 3734.67,4322.98 r270 top value=0.047uF
C70 "CL05A106MP5NUNC" 0402_070 3891,4337 r180 bottom value=10uF
C71 "GRM0335C1H4R7BA01D" 0201_033L 3722.86,4065.25 r270 top value=4.7pF
C72 "GRM033R6YA104KE14D" "FP-GRM033R6YA104KE14D_0201 (0603 Metric)-IPC_C" 4853.37,4217.48 r270 top
C73 "CL05A106MP5NUNC" 0402_070 3897,4303 r180 bottom value=10uF
C74 "CL03A225MQ3CRNC" 0201L 3945.46,4346.38 r180 bottom value=2.2uF
C75 "LMK063BJ224MP-F" 0201_033L 3945.46,4409.24 r180 bottom value=0.22uF
C76 "LMK063BJ224MP-F" 0201_033L 3945.46,4377.91 r180 bottom value=0.22uF
C77 "CL05A226MQ5N6J8" FP-CL05A226MQ5N6J8_0402-IPC_C 3415.03,4422.66 r0 top
C78 "CL05A106MP5NUNC" 0402_070 4038.9,4317.13 r180 bottom value=10uF
C79 "CL03A225MQ3CRNC" 0201L 4071.88,4346.34 r0 bottom value=2.2uF
C80 "LMK063BJ224MP-F" 0201_033L 4073.37,4377.75 r0 bottom value=0.22uF
C81 "LMK063BJ224MP-F" 0201_033L 4071.88,4409.36 r0 bottom value=0.22uF
C82 "CL05A106MP5NUNC" 0402_070 4001.02,4277.32 r0 bottom value=10uF
C83 "CL03A225MQ3CRNC" 0201L 4008.9,4346.15 r0 bottom value=2.2uF
C84 "LMK063BJ224MP-F" 0201_033L 4009.24,4377.83 r0 bottom value=0.22uF
C85 "LMK063BJ224MP-F" 0201_033L 4009.24,4409.33 r0 bottom value=0.22uF
C86 "GRM033R6YA104KE14D" "FP-GRM033R6YA104KE14D_0201 (0603 Metric)-IPC_C" 5910.41,3935.32 r0 bottom
C87 "LMK063BJ224MP-F" 0201_033L 4025.62,3891.02 r0 bottom value=0.22uF
C88 "LMK063BJ224MP-F" 0201_033L 4394.91,4124.76 r0 top value=0.22uF
C89 "CGB2A1X6S0J105K033BC" 0402L 3717.5,4135.45 r180 top value=1uF
C90 "CGB2A1X6S0J105K033BC" 0402L 3717.37,4182.85 r180 top value=1uF
C91 "GRM033R6YA104KE14D" "FP-GRM033R6YA104KE14D_0201 (0603 Metric)-IPC_C" 4292.99,4035.17 r180 bottom
C92 "GRM033R6YA104KE14D" "FP-GRM033R6YA104KE14D_0201 (0603 Metric)-IPC_C" 4065.74,3883.1 r90 bottom
C93 "CL05C120JB5NNNC" 0402L 6205.98,4550.46 r180 top value=12pF
C94 "LMK063BJ224MP-F" 0201_033L 4293.19,3964.68 r180 bottom value=0.22uF
C95 "LMK063BJ224MP-F" 0201_033L 3922.37,3891.76 r90 bottom value=0.22uF
C96 "LMK063BJ224MP-F" 0201_033L 4388.37,4235.76 r90 top value=0.22uF
C97 "LMK063BJ224MP-F" 0201_033L 3779.79,4050.2 r90 bottom value=0.22uF
C98 "LMK063BJ224MP-F" 0201_033L 4388.37,4297.76 r270 top value=0.22uF
C99 "GJM1555C1H1R8BB01D" 0402L 6328.98,4550.46 r180 top value=1.8pF
C100 "CL03A105MO3NRNH" FP-CL03A105MO3NRNH_0201-IPC_C 3741.24,3861.69 r0 bottom
C101 "GRM033R6YA104KE14D" "FP-GRM033R6YA104KE14D_0201 (0603 Metric)-IPC_C" 3741,3881.17 r0 bottom
C102 "CL03A225MQ3CRNC" 0201L 4393.22,4090.26 r0 top value=2.2uF
C103 "CL03A225MQ3CRNC" 0201L 4291.98,4058.8 r180 bottom value=2.2uF
C104 "GJM1555C1H1R8BB01D" 0402L 6450.41,4530.78 r270 top value=1.8pF
C105 "GRM033R6YA104KE14D" "FP-GRM033R6YA104KE14D_0201 (0603 Metric)-IPC_C" 5402.37,4347.37 r90 bottom
C106 "GRM155R71H472KA01D" 0402L 5574,4430.51 r270 bottom value=4700pF
C107 "GRM033R6YA104KE14D" "FP-GRM033R6YA104KE14D_0201 (0603 Metric)-IPC_C" 6223.22,4433.22 r90 top
C108 "GRM033R6YA104KE14D" "FP-GRM033R6YA104KE14D_0201 (0603 Metric)-IPC_C" 6197.97,3866.01 r270 top
C109 "GRM033R6YA104KE14D" "FP-GRM033R6YA104KE14D_0201 (0603 Metric)-IPC_C" 6365.6,3768.9 r0 top
C110 "GRM155R71H472KA01D" 0402L 6440,3773.61 r90 top value=4700pF
C114 "GRM033R6YA104KE14D" "FP-GRM033R6YA104KE14D_0201 (0603 Metric)-IPC_C" 5662.76,3747.34 r180 bottom
C115 "CL03A105MO3NRNH" FP-CL03A105MO3NRNH_0201-IPC_C 5685.98,3907.2 r0 top
C116 "CL03A105MO3NRNH" FP-CL03A105MO3NRNH_0201-IPC_C 5686.69,3878.74 r0 top
C117 "GRM033R6YA104KE14D" "FP-GRM033R6YA104KE14D_0201 (0603 Metric)-IPC_C" 5334.39,4536.81 r0 bottom locked
C118 "GRM033R6YA104KE14D" "FP-GRM033R6YA104KE14D_0201 (0603 Metric)-IPC_C" 5760.69,3733.87 r270 bottom
C119 "GRM033R6YA104KE14D" "FP-GRM033R6YA104KE14D_0201 (0603 Metric)-IPC_C" 5797.1,3909.21 r90 bottom
C120 "GRM033R6YA104KE14D" "FP-GRM033R6YA104KE14D_0201 (0603 Metric)-IPC_C" 4784.37,4437.46 r90 top
C122 "CL05A106MP5NUNC" 0402_070 6260,4040 r270 top value=10uF
C123 "GRM033R6YA104KE14D" "FP-GRM033R6YA104KE14D_0201 (0603 Metric)-IPC_C" 5489.38,3956.46 r180 bottom
C125 "CL03A103KA3NNNC" FP-CL03A103KA3NNNC_0201-IPC_C 5270.83,4102.9 r0 bottom locked
C126 "GRM033R6YA104KE14D" "FP-GRM033R6YA104KE14D_0201 (0603 Metric)-IPC_C" 3679.93,4262.91 r0 top
C127 "GRM033R6YA104KE14D" "FP-GRM033R6YA104KE14D_0201 (0603 Metric)-IPC_C" 6141.37,3936.75 r180 bottom
C128 "GRM033R6YA104KE14D" "FP-GRM033R6YA104KE14D_0201 (0603 Metric)-IPC_C" 6131.47,3761.12 r180 bottom
C129 "CL03A105MO3NRNH" FP-CL03A105MO3NRNH_0201-IPC_C 6207.77,3815.74 r270 bottom
C130 "GRM033R6YA104KE14D" "FP-GRM033R6YA104KE14D_0201 (0603 Metric)-IPC_C" 4251.69,4228 r180 bottom
D1 "NSR20F30NXT5G" DSN2_0603 3229.54,4211.99 r270 bottom value=30V
D2 "NSR20F30NXT5G" DSN2_0603 4603.84,3756.88 r0 top locked value=30V
Designator1 "Comment" MHNP_M2_PANHEAD_PHILLIPS 3109.58,4791.47 r0 top
Designator1_1 "BRAKE_WAY_HOLES1X2" BRAKE_WAY_HOLES1X2 3221.89,3788.2 r180 bottom
Designator2 "BRAKE_WAY_HOLES1X2" BRAKE_WAY_HOLES1X2 3778.11,4495.01 r180 top
Designator2_1 "BRAKE_WAY_HOLES1X2" BRAKE_WAY_HOLES1X2 3778.11,3788.2 r180 bottom
Designator3 "BRAKE_WAY_HOLES1X2" BRAKE_WAY_HOLES1X2 4273.11,4495.01 r180 top
Designator3_1 "BRAKE_WAY_HOLES1X2" BRAKE_WAY_HOLES1X2 4273.11,3788.2 r180 bottom
Designator4 "BRAKE_WAY_HOLES1X2" BRAKE_WAY_HOLES1X2 4688.11,4648.59 r180 top
Designator4_1 "BRAKE_WAY_HOLES1X2" BRAKE_WAY_HOLES1X2 4688.11,3650.25 r180 bottom
Designator5 "BRAKE_WAY_HOLES1X2" BRAKE_WAY_HOLES1X2 6176.11,4648.39 r180 top
Designator5_1 "BRAKE_WAY_HOLES1X2" BRAKE_WAY_HOLES1X2 6176.11,3650.45 r180 bottom
Designator5_2 "BRAKE_WAY_HOLES1X2" BRAKE_WAY_HOLES1X2 5433.11,3650.05 r180 bottom
Designator6 "Comment" MHNP_M2_PANHEAD_PHILLIPS 6500.3,4791.47 r0 top
Designator7 "Comment" MHNP_M2_PANHEAD_PHILLIPS 3109.58,3507.37 r0 top
Designator8 "Comment" MHNP_M2_PANHEAD_PHILLIPS 6500.3,3507.37 r0 top
Designator10 "BRAKE_WAY_HOLES1X2" BRAKE_WAY_HOLES1X2 3221.89,4495.01 r180 top
Designator22_1 "Comment" MHNP_2-5 5908.96,3794.29 r0 bottom
Designator23 "Comment" MHNP_2-5 5014.62,3794.28 r0 bottom locked
FID1 "Fiducial" FIDUCIAL6.4-20 3259.58,3507.37 r0 top
FID2 "Fiducial" FIDUCIAL6.4-20 3259.58,4791.47 r0 top
FID3 "Fiducial" FIDUCIAL6.4-20 6350.3,3507.37 r0 top
FID4 "Fiducial" FIDUCIAL6.4-20 6350.3,3507.37 r180 bottom
FID5 "Fiducial" FIDUCIAL6.4-20 3259.58,4791.47 r180 bottom
FID6 "Fiducial" FIDUCIAL6.4-20 3259.58,3507.37 r180 bottom
FL1 "BLM15PD300SZ1D" 0402L 3949.54,4288.55 r90 bottom
FL2 "BLM15PD300SZ1D" 0402L 3228.8,4133.28 r90 bottom
FL3 "BLM15PD300SZ1D" 0402L 6159,3836 r270 top
FL6 "BLM15PD300SZ1D" 0402L 3153.46,4388.19 r180 top
FL7 "BLM15PD300SZ1D" 0402L 3835,4188.31 r90 bottom
FL8 "BLM15PD300SZ1D" 0402L 4170.37,4339.04 r180 bottom
FL9 "BLM15PD300SZ1D" 0402L 3881.31,4271 r180 bottom
FL10 "BLM15PD300SZ1D" 0402L 3978.37,3984.87 r0 bottom
FL11 "BLM15PD300SZ1D" 0402L 4674.94,3755.5 r180 top locked
FL12 "BLM15PD300SZ1D" 0402L 5450.1,4210.46 r180 bottom
FL14 "BLM15PD300SZ1D" 0402L 6330,4105.18 r180 top
FL20 "BLM15PD300SZ1D" 0402L 3552.13,4385.05 r180 top
FL22 "BLM15PD300SZ1D" 0402L 4843.47,3842.73 r270 top locked
J1 "105017-0001" CONN_105017-0001 3119.51,4164.78 r90 bottom
J2 "QSH-030-01-L-D-A" Samtec_QSH-030-01-X-D-A 4733.36,4144.5 r0 bottom locked
J3 "M50-3930442" FP-M50-3930442_HDR4-RECOMMENDED_LAND_PATTERN 5065.29,4581.75 r0 bottom
J4 "51441-1093" FP-51441-1093_CONN_SMD_FFC-0 4585.45,4173.34 r270 top locked
J5 "105017-0001" CONN_105017-0001 6486.85,4155.73 r90 top
J6 "51441-1093" FP-51441-1093_CONN_SMD_FFC-0 5633.17,3775.17 r0 top
J7 "GRPB052MWCN-RC" FP-GRPB052MWCN-RC_HDR10-MFG 5736.47,4571.46 r0 bottom
J8 "M50-3930342" FP-M50-3930342_HDR3-MFG 5459.37,4574.83 r0 bottom
J9 "U.FL-R-SMT-1(01)" CONN_UFL-R-SMT-1 5232.96,4283.6 r90 top
J10 "M50-3930342" FP-M50-3930342_HDR3-MFG 6582.37,3800 r90 top
L1 "LQG15HS2N4S02D" IND_LQG15H 5975.41,4324.41 r0 top value=2.4nH
L2 "MCKK2012TR47M" "FP-MCKK2012TR47M_0805 (2012 Metric)-IPC_C" 3480.98,4358.44 r270 top
L3 "MCKK2012TR47M" "FP-MCKK2012TR47M_0805 (2012 Metric)-IPC_C" 3346.24,4358.44 r270 top
L4 "MCKK2012TR47M" "FP-MCKK2012TR47M_0805 (2012 Metric)-IPC_C" 3480.98,3957.6 r90 top
L5 "MCKK2012TR47M" "FP-MCKK2012TR47M_0805 (2012 Metric)-IPC_C" 3344.24,3957.6 r90 top
L6 "LQG15HS2N4S02D" IND_LQG15H 5903.37,4396.46 r90 top value=2.4nH
L7 "MLZ2012N6R8LT000" 0805_HV 5980.15,4040.83 r90 bottom value=6.8uH
L8 "BLM18HE152SN1D" 0603L 6040.76,3919.1 r90 top value="1500 ohm"
L9 "LQG15HS2N0S02D" IND_LQG15H 5930.04,4485.35 r90 top value=2nH
L10 "LQG15HS2N0S02D" IND_LQG15H 6085.98,4550.46 r0 top value=2nH
L11 "BLM18SG260TN1D" 0603L 3892.39,4015.02 r0 bottom value="26 ohm"
L12 "BLM18SG260TN1D" 0603L 4090.19,4281.1 r180 bottom value="26 ohm"
L13 "BLM18SG260TN1D" 0603L 3242.64,4385.23 r180 top value="26 ohm"
L14 "BLM18SG260TN1D" 0603L 4121.43,4229.06 r180 bottom value="26 ohm"
LD1 "APHHS1005CGCK" APHHS1005_Green 3121.65,4188.5 r0 top value=Green
LD2 "APHHS1005CGCK" APHHS1005_Green 4607.12,4561.07 r180 top locked value=Green
LD3 "APHHS1005CGCK" APHHS1005_Green 4758.14,4558.15 r0 top value=Green
LD4 "APHHS1005CGCK" APHHS1005_Green 3600,4117.07 r0 top value=Green
LD5 "APHHS1005CGCK" APHHS1005_Green 4996.12,4338.02 r270 top value=Green
LD6 "APHHS1005CGCK" APHHS1005_Green 5736.37,4393.36 r90 top value=Green
Q1 "BSS123-7-F" FP-BSS123-7-F_SOT23-IPC_C 5082.37,4240.81 r90 top
R1 "RR0306P-103-D" FP-RR0306P-103-D_0201-IPC_C 5577.06,4028.97 r90 bottom
R2 "RC0201JR-070RL" "FP-RC0201JR-070RL_0201 (0603 Metric)-MFG" 4295.7,4110.3 r270 bottom
R3 "RR0306P-103-D" FP-RR0306P-103-D_0201-IPC_C 3793.63,3912.76 r180 bottom
R4 "CRCW0201100KFKED" 0201L 3717.54,4429.01 r180 top value=100k
R5 "CRCW0201100KFKED" 0201L 4378.13,4374.27 r270 top value=100k
R6 "CRCW020133R2FNED" 0201L 3706.27,4022.49 r270 bottom value=33.2
R7 "RR0306P-103-D" FP-RR0306P-103-D_0201-IPC_C 3944.52,3889.21 r90 bottom
R8 "RR0306P-103-D" FP-RR0306P-103-D_0201-IPC_C 3916.9,3972.12 r180 bottom
R9 "CRCW0201100KFKED" 0201L 3835,3920.2 r270 bottom value=100k
R10 "AC0201FR-0720RL" FP-AC0201FR-0720RL_0201-IPC_C 4917.01,3921 r180 bottom
R11 "AC0201FR-0720RL" FP-AC0201FR-0720RL_0201-IPC_C 4950.01,3937.94 r180 bottom
R12 "RC0201JR-070RL" "FP-RC0201JR-070RL_0201 (0603 Metric)-MFG" 4929.17,4495.46 r0 bottom
R13 "RC0201JR-07220RL" 0201L 4636.42,4516.76 r180 top locked value=220
R14 "RC0201JR-070RL" "FP-RC0201JR-070RL_0201 (0603 Metric)-MFG" 4886,4506.26 r90 top
R15 "RC0201JR-07220RL" 0201L 3663,4121.49 r90 top value=220
R16 "RC0201FR-077K87L" 0201L 5566.39,4484.46 r180 top value=7.87k
R17 "RC0201JR-07220RL" 0201L 5736.37,4328.17 r90 top value=220
R18 "RR0306P-103-D" FP-RR0306P-103-D_0201-IPC_C 5363.78,4038.98 r270 bottom
R19 "RR0306P-103-D" FP-RR0306P-103-D_0201-IPC_C 3605.65,4252.67 r270 top
R20 "RR0306P-103-D" FP-RR0306P-103-D_0201-IPC_C 6072.37,3988.94 r180 bottom
R21 "RR0306P-103-D" FP-RR0306P-103-D_0201-IPC_C 4318.97,4310.76 r0 bottom
R22 "RR0306P-103-D" FP-RR0306P-103-D_0201-IPC_C 4318.97,4288.76 r0 bottom
R23 "RR0306P-103-D" FP-RR0306P-103-D_0201-IPC_C 4301.24,4249.29 r0 bottom
R24 "CRCW0402200RFKEDHP" FP-CRCW0402200RFKEDHP_0402-IPC_C 6071.37,3937.46 r180 bottom
R25 "RC0201FR-074K99L" 0201L 3292.98,4200.49 r180 top value=4.99k
R26 "RC0201FR-074K99L" 0201L 3292.13,4116.99 r180 top value=4.99k
R27 "RC0201JR-07510RL" 0201L 6094.58,3752.54 r90 bottom value=510
R28 "RC0201JR-070RL" "FP-RC0201JR-070RL_0201 (0603 Metric)-MFG" 3538.8,4195 r180 top
R29 "CRCW0201100KFKED" 0201L 6072.37,3965.94 r180 bottom value=100k
R30 "RC0201JR-070RL" "FP-RC0201JR-070RL_0201 (0603 Metric)-MFG" 5221.5,4404.87 r0 bottom locked
R31 "RC0201JR-070RL" "FP-RC0201JR-070RL_0201 (0603 Metric)-MFG" 5010.5,4008.93 r0 bottom
R32 "RC0201JR-070RL" "FP-RC0201JR-070RL_0201 (0603 Metric)-MFG" 3539.13,4171 r180 top
R33 "RC0201FR-074K99L" 0201L 3292.13,4088.65 r180 top value=4.99k
R34 "RC0201FR-074K99L" 0201L 3541.5,4220.5 r0 top value=4.99k
R35 "RR0306P-103-D" FP-RR0306P-103-D_0201-IPC_C 3292.52,4231 r180 top
R36 "RR0306P-103-D" FP-RR0306P-103-D_0201-IPC_C 3524.56,4098.79 r270 top
R37 "CRCW0201100KFKED" 0201L 5009.23,3983.33 r180 bottom value=100k
R38 "RC0201FR-074K99L" 0201L 5282.68,4235.46 r0 bottom value=4.99k
R39 "RC0201JR-07510RL" 0201L 3090.67,4224.06 r0 top value=510
R40 "RC0201FR-074K99L" 0201L 3660.79,4145.37 r0 bottom value=4.99k
R41 "RC0201JR-070RL" "FP-RC0201JR-070RL_0201 (0603 Metric)-MFG" 3825.31,4374.62 r90 bottom
R42 "RC0201JR-07220RL" 0201L 4799.25,4494.23 r270 top locked value=220
R43 "RR0306P-103-D" FP-RR0306P-103-D_0201-IPC_C 3630.7,3875.43 r0 bottom
R44 "RR0306P-103-D" FP-RR0306P-103-D_0201-IPC_C 3619.37,4059.85 r0 bottom
R45 "RR0306P-103-D" FP-RR0306P-103-D_0201-IPC_C 3809.22,3978.91 r0 bottom
R46 "CRCW020133R2FNED" 0201L 3595.37,3913.81 r90 bottom value=33.2
R47 "CRCW020133R2FNED" 0201L 3734.37,4022.49 r270 bottom value=33.2
R48 "CRCW020133R2FNED" 0201L 3608.37,4021.09 r270 bottom value=33.2
R49 "CRCW020133R2FNED" 0201L 3771.3,3947.76 r270 bottom value=33.2
R50 "RC0201JR-071KL" 0201L 3197.4,4327.73 r0 top value=1.0k
R51 "RC0201JR-070RL" "FP-RC0201JR-070RL_0201 (0603 Metric)-MFG" 5230.37,4240.37 r270 bottom locked
R52 "RC0201FR-071K96L" 0201L 3141.4,4327.36 r0 top value=1.96k
R53 "RC0402FR-073R83L" "FP-RC0402FR-073R83L_0402 (1005 Metric)-IPC_C" 3532.13,4316.35 r90 top
R54 "RC0402FR-073R83L" "FP-RC0402FR-073R83L_0402 (1005 Metric)-IPC_C" 3295.13,4316.07 r90 top
R55 "RC0402FR-073R83L" "FP-RC0402FR-073R83L_0402 (1005 Metric)-IPC_C" 3544.13,3985.35 r180 top
R56 "RC0402FR-073R83L" "FP-RC0402FR-073R83L_0402 (1005 Metric)-IPC_C" 3279.13,3985.21 r0 top
R57 "RC0201JR-070RL" "FP-RC0201JR-070RL_0201 (0603 Metric)-MFG" 5180.56,4149.19 r270 bottom locked
R58 "RC0201JR-070RL" "FP-RC0201JR-070RL_0201 (0603 Metric)-MFG" 5008.99,4036.94 r180 bottom
R59 "RR0306P-103-D" FP-RR0306P-103-D_0201-IPC_C 4301.24,4224.76 r0 bottom
R60 "RC0201JR-070RL" "FP-RC0201JR-070RL_0201 (0603 Metric)-MFG" 3846.82,4374.62 r90 bottom
R61 "RC0201JR-070RL" "FP-RC0201JR-070RL_0201 (0603 Metric)-MFG" 3577.24,4245.78 r270 bottom
R62 "RC0201JR-070RL" "FP-RC0201JR-070RL_0201 (0603 Metric)-MFG" 3662,4416.56 r90 bottom
R63 "RC0201JR-070RL" "FP-RC0201JR-070RL_0201 (0603 Metric)-MFG" 3604,4154.79 r270 bottom
R64 "RC0201FR-074K99L" 0201L 3715.38,4103.78 r90 bottom value=4.99k
R65 "RR0306P-103-D" FP-RR0306P-103-D_0201-IPC_C 3708.05,4143.04 r0 bottom
R66 "RC0201JR-070RL" "FP-RC0201JR-070RL_0201 (0603 Metric)-IPC_C" 4982.89,4434.77 r0 top
R67 "RC0201JR-070RL" "FP-RC0201JR-070RL_0201 (0603 Metric)-MFG" 5508.37,3935.46 r0 bottom
R68 "RC0201JR-070RL" "FP-RC0201JR-070RL_0201 (0603 Metric)-MFG" 5508.37,3935.46 r0 top
R69 "RC0201FR-074K99L" 0201L 5511.07,3729.96 r0 bottom value=4.99k
R70 "RC0201JR-070RL" "FP-RC0201JR-070RL_0201 (0603 Metric)-MFG" 5435.37,3870.14 r0 bottom
R71 "RC0201JR-070RL" "FP-RC0201JR-070RL_0201 (0603 Metric)-MFG" 5383.33,3793.46 r270 bottom
R72 "RC0201JR-070RL" "FP-RC0201JR-070RL_0201 (0603 METRIC)-IPC_C" 5433.38,3894.46 r180 bottom
R73 "RC0201JR-070RL" "FP-RC0201JR-070RL_0201 (0603 METRIC)-IPC_C" 5433.37,3917.06 r180 bottom
R74 "RC0201JR-070RL" "FP-RC0201JR-070RL_0201 (0603 METRIC)-IPC_C" 4896.36,3879.46 r0 top locked
R75 "RC0201JR-071KL" 0201L 3875.37,3907.8 r270 bottom value=1.0k
R76 "RC0201JR-070RL" "FP-RC0201JR-070RL_0201 (0603 METRIC)-IPC_C" 5698.97,3903.45 r90 bottom
R77 "RR0306P-103-D" FP-RR0306P-103-D_0201-IPC_C 5163.43,4030.06 r270 bottom locked
R78 "RR0306P-103-D" FP-RR0306P-103-D_0201-IPC_C 5164.52,3976.35 r270 bottom locked
R79 "ERJ-1GNF4701C" FP-ERJ-1GNF4701C_0201-IPC_C 5788.67,3846.46 r90 bottom
R80 "RR0306P-103-D" FP-RR0306P-103-D_0201-IPC_C 5123,3920.48 r90 bottom
R81 "RR0306P-103-D" FP-RR0306P-103-D_0201-IPC_C 5344.92,4081.19 r180 bottom locked
R82 "RR0306P-103-D" FP-RR0306P-103-D_0201-IPC_C 5272.85,4040.2 r270 bottom
R83 "RR0306P-103-D" FP-RR0306P-103-D_0201-IPC_C 4277.8,4155.3 r180 bottom
R84 "RR0306P-103-D" FP-RR0306P-103-D_0201-IPC_C 4119.89,3922.4 r0 bottom
R85 "RR0306P-103-D" FP-RR0306P-103-D_0201-IPC_C 4355.44,4224.99 r0 bottom
R86 "RC0201JR-070RL" "FP-RC0201JR-070RL_0201 (0603 METRIC)-IPC_C" 5629.22,4180.57 r0 top
R87 "RC0201JR-070RL" "FP-RC0201JR-070RL_0201 (0603 METRIC)-IPC_C" 5629.37,4202.46 r0 top
R88 "AC0201FR-0720RL" FP-AC0201FR-0720RL_0201-IPC_C 4778.18,4060.33 r180 top locked
R89 "CRCW0201100KFKED" 0201L 5826.38,4411.08 r0 top value=100k
R90 "RC0201JR-070RL" "FP-RC0201JR-070RL_0201 (0603 METRIC)-IPC_C" 5837.39,4321.29 r180 bottom
R91 "RC0201JR-070RL" "FP-RC0201JR-070RL_0201 (0603 METRIC)-IPC_C" 5910.14,3926.46 r180 top
R92 "CRCW0201100KFKED" 0201L 6039.37,3742.65 r270 bottom value=100k
R93 "RR0306P-103-D" FP-RR0306P-103-D_0201-IPC_C 5126.93,4030.08 r90 bottom locked
R94 "RR0306P-103-D" FP-RR0306P-103-D_0201-IPC_C 5286.18,4537.08 r0 bottom locked
R95 "RR0306P-103-D" FP-RR0306P-103-D_0201-IPC_C 5222.16,4444.39 r180 bottom locked
R96 "RR0306P-103-D" FP-RR0306P-103-D_0201-IPC_C 5162.8,3928.09 r90 bottom locked
R97 "RC0201JR-070RL" "FP-RC0201JR-070RL_0201 (0603 METRIC)-IPC_C" 5309.27,4040.92 r90 bottom
R98 "RR0306P-103-D" FP-RR0306P-103-D_0201-IPC_C 5128.47,3976.25 r90 bottom locked
R99 "RC0201JR-070RL" "FP-RC0201JR-070RL_0201 (0603 METRIC)-IPC_C" 5222.1,4479.52 r180 bottom locked
R100 "RC0201JR-070RL" "FP-RC0201JR-070RL_0201 (0603 METRIC)-IPC_C" 5320.66,4357.38 r0 bottom
R101 "RC0201JR-070RL" "FP-RC0201JR-070RL_0201 (0603 METRIC)-IPC_C" 5222.36,4510.46 r180 bottom
R102 "RC0201JR-070RL" "FP-RC0201JR-070RL_0201 (0603 METRIC)-IPC_C" 5792.03,4320.41 r0 bottom
R103 "RC0201JR-070RL" "FP-RC0201JR-070RL_0201 (0603 METRIC)-IPC_C" 4355.64,4245.1 r0 bottom
R104 "RR0306P-103-D" FP-RR0306P-103-D_0201-IPC_C 4966.89,3965.95 r0 top locked
R105 "RC0201JR-070RL" "FP-RC0201JR-070RL_0201 (0603 METRIC)-IPC_C" 4865.78,3995.57 r90 top
R106 "RC0201JR-070RL" "FP-RC0201JR-070RL_0201 (0603 METRIC)-IPC_C" 4902.35,3985.56 r0 top locked
R107 "RC0201JR-07510RL" 0201L 5063.61,4357.18 r180 top value=510
R108 "RC0201JR-07510RL" 0201L 5035.32,4159.98 r0 top value=510
R109 "RC0201JR-070RL" "FP-RC0201JR-070RL_0201 (0603 Metric)-MFG" 3732.14,4012.38 r0 top
R110 "RR0306P-103-D" FP-RR0306P-103-D_0201-IPC_C 5309.89,3724.46 r0 top
R111 "RC0201JR-07220RL" 0201L 5137.39,4116.46 r0 top value=220
R112 "RC0201JR-070RL" "FP-RC0201JR-070RL_0201 (0603 METRIC)-IPC_C" 5259.36,4367.46 r0 bottom
R113 "RC0201JR-070RL" "FP-RC0201JR-070RL_0201 (0603 METRIC)-IPC_C" 5258.37,4445.48 r270 top
R114 "CRCW040261R9FKED" 0402L 6397.76,3909.29 r270 top value=61.9
R115 "RC0201JR-070RL" "FP-RC0201JR-070RL_0201 (0603 Metric)-IPC_C" 6342.98,3961 r0 top
R116 "RC0201JR-070RL" "FP-RC0201JR-070RL_0201 (0603 Metric)-IPC_C" 6242.98,3956 r0 top
R117 "CRCW040261R9FKED" 0402L 6397.85,3823.52 r270 top value=61.9
R118 "RR0306P-103-D" FP-RR0306P-103-D_0201-IPC_C 6185,4422 r90 top
R119 "CRCW040261R9FKED" 0402L 5520.06,4410.82 r180 bottom value=61.9
R120 "RC0201JR-070RL" "FP-RC0201JR-070RL_0201 (0603 Metric)-IPC_C" 6291,4252.99 r90 top
R121 "RC0201JR-070RL" "FP-RC0201JR-070RL_0201 (0603 METRIC)-IPC_C" 6137.23,4333.23 r180 top
R122 "RR0306P-103-D" FP-RR0306P-103-D_0201-IPC_C 5568.37,4347.11 r270 bottom
R123 "RC0201JR-070RL" "FP-RC0201JR-070RL_0201 (0603 METRIC)-IPC_C" 5562.87,4257.76 r90 bottom
R124 "RR0306P-103-D" FP-RR0306P-103-D_0201-IPC_C 4864.68,4471.7 r0 top
R125 "RR0306P-103-D" FP-RR0306P-103-D_0201-IPC_C 5087.65,3914.04 r0 top
R126 "CRCW040261R9FKED" 0402L 5445.1,4410.54 r180 bottom value=61.9
R127 "RC0201JR-070RL" "FP-RC0201JR-070RL_0201 (0603 METRIC)-IPC_C" 6137.99,4310 r0 top
R128 "RC0201JR-070RL" "FP-RC0201JR-070RL_0201 (0603 METRIC)-IPC_C" 6183.91,4240.71 r180 top
R129 "RC0201JR-070RL" "FP-RC0201JR-070RL_0201 (0603 METRIC)-IPC_C" 5125.2,3925.93 r90 top
R130 "AC0201FR-0720RL" FP-AC0201FR-0720RL_0201-IPC_C 4617.95,4372.15 r270 top locked
R131 "RC0201JR-070RL" "FP-RC0201JR-070RL_0201 (0603 METRIC)-IPC_C" 5809.36,3978.41 r180 bottom
R132 "AC0201FR-0720RL" FP-AC0201FR-0720RL_0201-IPC_C 4777.33,4090.57 r180 top locked
R133 "AC0201FR-0720RL" FP-AC0201FR-0720RL_0201-IPC_C 4740.67,4227.63 r180 top locked
R134 "RR0306P-103-D" FP-RR0306P-103-D_0201-IPC_C 6388.49,3961 r0 top
R135 "AC0201FR-0720RL" FP-AC0201FR-0720RL_0201-IPC_C 4722.06,4196.8 r180 top locked
R136 "RC0201JR-070RL" "FP-RC0201JR-070RL_0201 (0603 Metric)-IPC_C" 6238.01,4241 r0 top
R137 "AC0201FR-0720RL" FP-AC0201FR-0720RL_0201-IPC_C 4681.54,3924.7 r90 top locked
R138 "AC0201FR-0720RL" FP-AC0201FR-0720RL_0201-IPC_C 4767.38,4284.46 r180 top
R139 "RC0201JR-070RL" "FP-RC0201JR-070RL_0201 (0603 Metric)-IPC_C" 6313,4252.99 r270 top
R140 "AC0201FR-0720RL" FP-AC0201FR-0720RL_0201-IPC_C 4714.81,3924.69 r90 top locked
R141 "RC0201FR-074K99L" 0201L 6248.22,4429.26 r90 top value=4.99k
R158 "RC0201FR-0782K5L" 0201L 4228.2,4119.6 r0 bottom value=82.5k
R159 "RC0201JR-07750RL" 0201L 4223.5,4078.1 r270 bottom value=750
R160 "RC0201JR-070RL" "FP-RC0201JR-070RL_0201 (0603 METRIC)-IPC_C" 5768.53,3903.27 r90 bottom
R161 "RC0201JR-070RL" "FP-RC0201JR-070RL_0201 (0603 METRIC)-IPC_C" 5629.37,4158.46 r0 top
R166 "RC0201JR-070RL" "FP-RC0201JR-070RL_0201 (0603 METRIC)-IPC_C" 5728.8,3903.59 r90 bottom
R168 "RC0201JR-070RL" "FP-RC0201JR-070RL_0201 (0603 METRIC)-IPC_C" 5653.43,3903.57 r90 bottom
R170 "RC0201FR-0782K5L" 0201L 4154.35,3946.46 r180 bottom value=82.5k
R171 "RC0201JR-07750RL" 0201L 4204.44,3980.18 r0 bottom value=750
R172 "RC0201FR-0782K5L" 0201L 4401.11,4142.03 r90 bottom value=82.5k
R174 "RC0201FR-077K87L" 0201L 4269.1,4113.8 r90 bottom value=7.87k
R176 "RC0201FR-077K87L" 0201L 4389.6,4181.8 r0 bottom value=7.87k
R177 "RR0306P-103-D" FP-RR0306P-103-D_0201-IPC_C 4849.59,4099.95 r90 top
R178 "RR0306P-103-D" FP-RR0306P-103-D_0201-IPC_C 4918.69,4169.46 r180 top
R180 "ERJ-1GNF4701C" FP-ERJ-1GNF4701C_0201-IPC_C 5653.37,3789.15 r270 bottom
R181 "ERJ-1GNF4701C" FP-ERJ-1GNF4701C_0201-IPC_C 5639.79,3901.65 r90 top
R182 "RC0201JR-070RL" "FP-RC0201JR-070RL_0201 (0603 METRIC)-IPC_C" 4650.14,4371.83 r270 top locked
R183 "RC0201JR-070RL" "FP-RC0201JR-070RL_0201 (0603 METRIC)-IPC_C" 5593.19,3884.84 r90 top
R184 "RC0201JR-070RL" "FP-RC0201JR-070RL_0201 (0603 METRIC)-IPC_C" 5562.38,3883.78 r90 top
R185 "RC0201JR-070RL" "FP-RC0201JR-070RL_0201 (0603 METRIC)-IPC_C" 5521.36,3882.46 r180 top
RA1 "EXB-18VR000X" FP-EXB-18VR000X_0502-MFG 4733.17,4479.49 r180 top locked
RA2 "EXB-18VR000X" FP-EXB-18VR000X_0502-MFG 4580.6,4423.99 r180 top locked
RA3 "EXB-18VR000X" FP-EXB-18VR000X_0502-MFG 4772.94,3873.84 r0 top locked
RA4 "EXB-18VR000X" FP-EXB-18VR000X_0502-MFG 4620.57,3957.49 r0 top locked
RA5 "EXB-18VR000X" FP-EXB-18VR000X_0502-MFG 4941.51,4432.71 r90 bottom locked
RA6 "EXB-18VR000X" FP-EXB-18VR000X_0502-MFG 4941.09,4327.39 r90 bottom locked
RA7 "EXB-18VR000X" FP-EXB-18VR000X_0502-MFG 4942.52,4213.65 r90 bottom locked
RA8 "EXB-18VR000X" FP-EXB-18VR000X_0502-MFG 4941.86,4095.87 r90 bottom locked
